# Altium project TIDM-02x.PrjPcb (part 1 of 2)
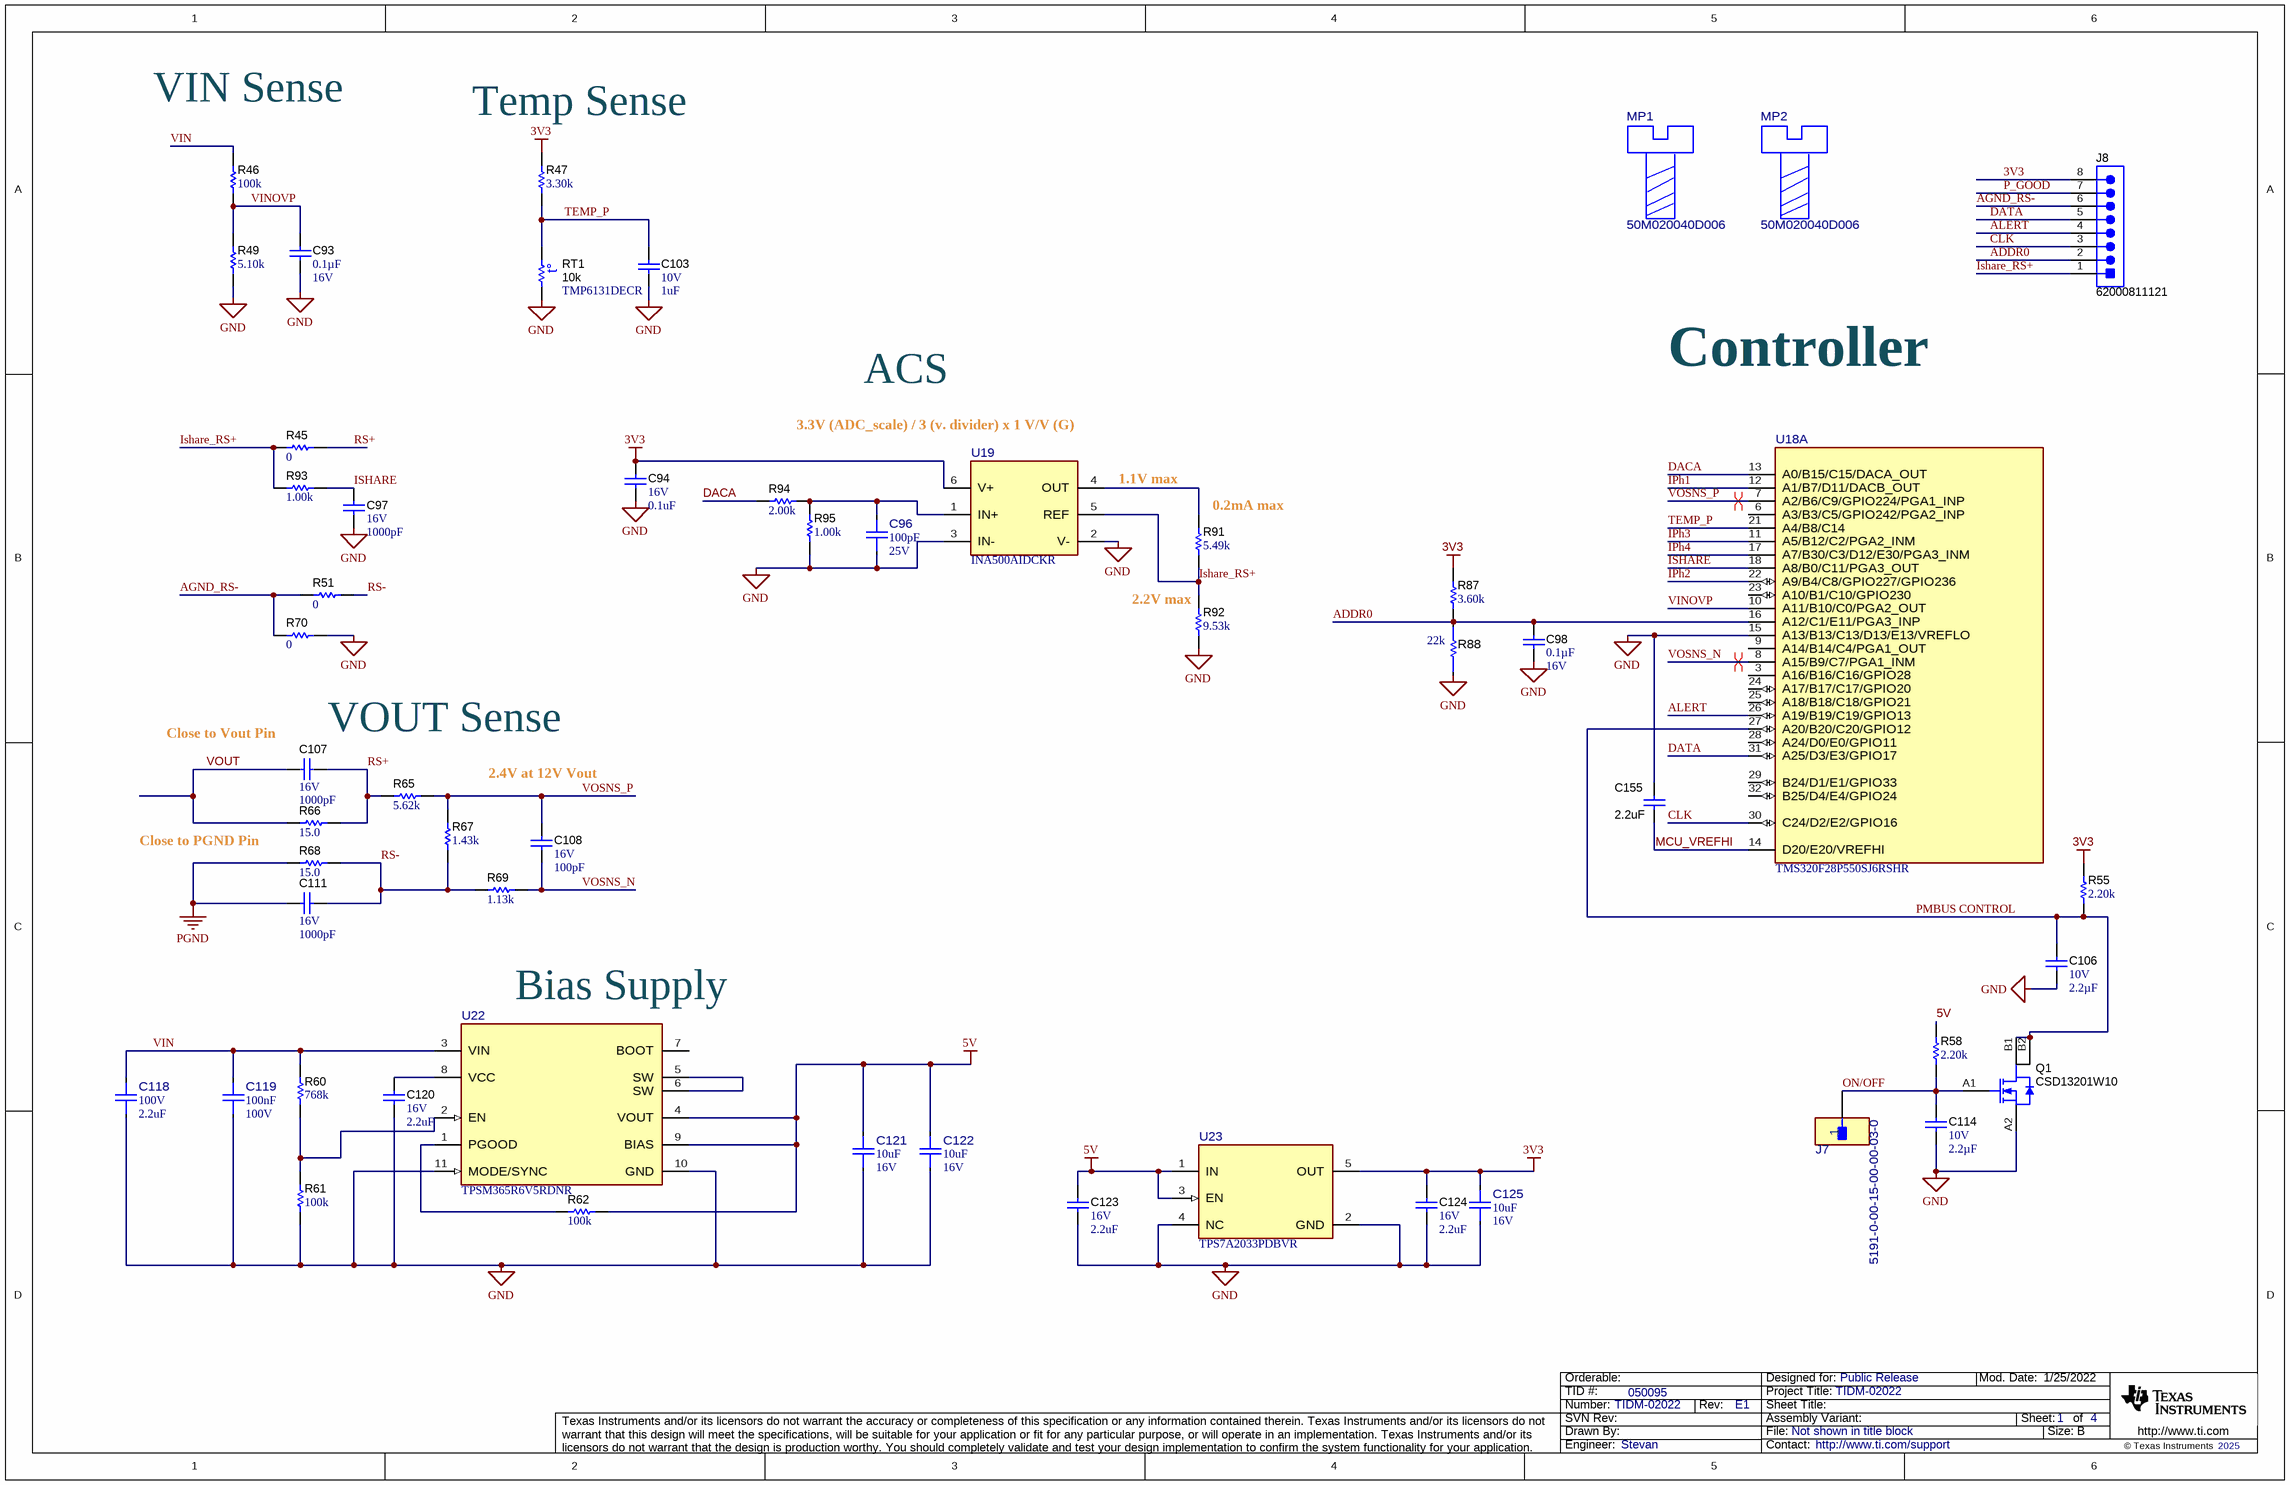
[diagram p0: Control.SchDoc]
CopyrightYear: 2025; PCB_Layout: Stevan; PCB_Rev: E1; PRJ_Customer: Public Release; PRJ_Engineer: Stevan; PRJ_Number: TIDM-02022; PRJ_Title: TIDM-02022; SCH_Rev: E1; TechSupport: http://www.ti.com/support; TID: 050095
4 sheets, 252 parts. Net scope: global (net labels, ports and power ports of the same name join across sheets).
Board file: TIDM-02022.PcbDoc
Sheets:
  Control.SchDoc
  MCU_Support.SchDoc
  PowerStage.SchDoc
  TIDA-05x_Hardware.SchDoc

## Sheet Control.SchDoc
size 431 x 279 mm; Date: Not shown in title block; ApprovedBy: Not shown in title block; CheckedBy: Not shown in title block; Author: Not shown in title block; CompanyName: Not shown in title block; Engineer: Not shown in title block; Organization: Not shown in title block; Address1: Not shown in title block; Address2: Not shown in title block; Address3: Not shown in title block; Address4: Not shown in title block; DocumentNumber: 2; Revision: Use project parameter SCH_Rev; SheetNumber: 1; SheetTotal: 4; PageSetup: Record=PageOptions¦CenterHorizontal=True¦CenterVertical=True¦PrintScale=1.00¦XCorrection=1.00¦YCorrection=1.00¦PrintKind=0¦BorderSize=5000000¦LeftOffset=0¦BottomOffset=0¦Orientation=2¦PaperLength=1000¦PaperWidth=1000¦Scale=100¦PaperSource=15¦PrintQuality=600¦MediaType=1¦DitherType=10¦PaperKind=Letter¦PrintScaleMode=1

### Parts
C93  ValueDisplayed: 0.1µF  VDC_V: 16V  [0201_033]  (hidden comment: 0201BB104KW160)
C94  VDC_V: 16V  ValueDisplayed: 0.1uF  [0201]  (hidden comment: GRM033Z71C104KE14D)
C96  ValueDisplayed: 100pF  VDC_V: 25V  [FP-250R05L101FV4T_0201-MFG]  (hidden comment: 250R05L101FV4T)
C97  VDC_V: 16V  ValueDisplayed: 1000pF  [0201]  (hidden comment: GRM033R71C102KA01D)
C98  ValueDisplayed: 0.1µF  VDC_V: 16V  [0201_033]  (hidden comment: 0201BB104KW160)
C103  VDC_V: 10V  ValueDisplayed: 1uF  [0201]  (hidden comment: CL03A105MP3NSNC)
C106  VDC_V: 10V  ValueDisplayed: 2.2µF  [0201_040]  (hidden comment: GRM033R61A225KE47D)
C107  VDC_V: 16V  ValueDisplayed: 1000pF  [0201_Silk]  (hidden comment: GRM033R71C102KA01D)
C108  VDC_V: 16V  ValueDisplayed: 100pF  [0201]  (hidden comment: GRM033R71C101KA01D)
C111  VDC_V: 16V  ValueDisplayed: 1000pF  [0201_Silk]  (hidden comment: GRM033R71C102KA01D)
C114  VDC_V: 10V  ValueDisplayed: 2.2µF  [0201_040]  (hidden comment: GRM033R61A225KE47D)
C118  VDC_V: 100V  ValueDisplayed: 2.2uF  [FP-12061C225KAT2A_1206-IPC_C]  (hidden comment: 12061C225KAT2A)
C119  Cap_F: 100nF  VDC_V: 100V  [FP-06031C104K4T2A_0603-IPC_C]  (hidden comment: 06031C104K4T2A)
C120  VDC_V: 16V  ValueDisplayed: 2.2uF  [0402S]  (hidden comment: C1005X5R1C225K050BC)
C121  ValueDisplayed: 10uF  VDC_V: 16V  [FP-GRT188R61C106KE13D_0603-MFG]  (hidden comment: GRT188R61C106KE13D)
C122  ValueDisplayed: 10uF  VDC_V: 16V  [FP-GRT188R61C106KE13D_0603-MFG]  (hidden comment: GRT188R61C106KE13D)
C123  VDC_V: 16V  ValueDisplayed: 2.2uF  [0402S]  (hidden comment: C1005X5R1C225K050BC)
C124  VDC_V: 16V  ValueDisplayed: 2.2uF  [0402S]  (hidden comment: C1005X5R1C225K050BC)
C125  ValueDisplayed: 10uF  VDC_V: 16V  [FP-GRT188R61C106KE13D_0603-MFG]  (hidden comment: GRT188R61C106KE13D)
C155  ValueDisplayed: 2.2uF  [0603]  (hidden comment: 885012106018)
J7  5191-0-00-15-00-00-03-0  [FP-5191-0-00-15-00-00-03-0_CONN_PIN-MFG]
J8  62000811121  [Wurth_62000811121]
MP1  50M020040D006  [FP-50M020040D006_M2_NYLON_SCREW-MFG]
MP2  50M020040D006  [FP-50M020040D006_M2_NYLON_SCREW-MFG]
Q1  CSD13201W10  [YZB0004AEAE]
R45  ValueDisplayed: 0  [0201_Silk]  (hidden comment: CRCW02010000Z0ED)
R46  ValueDisplayed: 100k  [0402]  (hidden comment: CRCW0402100KDHEDP)
R47  ValueDisplayed: 3.30k  [0201]  (hidden comment: RC0201FR-073K3L)
R49  ValueDisplayed: 5.10k  [0201]  (hidden comment: RC0201FR-075K1L)
R51  ValueDisplayed: 0  [0201_Silk]  (hidden comment: CRCW02010000Z0ED)
R55  ValueDisplayed: 2.20k  [0201]  (hidden comment: RC0201FR-7D2K2L)
R58  ValueDisplayed: 2.20k  [0201]  (hidden comment: RC0201FR-7D2K2L)
R60  ValueDisplayed: 768k  [0201]  (hidden comment: RC0201FR-07768KL)
R61  ValueDisplayed: 100k  [0201]  (hidden comment: RC0201FR-07100KL)
R62  ValueDisplayed: 100k  [0201]  (hidden comment: RC0201FR-07100KL)
R65  ValueDisplayed: 5.62k  [0201]  (hidden comment: RC0201FR-075K62L)
R66  ValueDisplayed: 15.0  [0201_Silk]  (hidden comment: RC0201FR-0715RL)
R67  ValueDisplayed: 1.43k  [0201]  (hidden comment: RC0201FR-071K43L)
R68  ValueDisplayed: 15.0  [0201_Silk]  (hidden comment: RC0201FR-0715RL)
R69  ValueDisplayed: 1.13k  [0201]  (hidden comment: RC0201FR-071K13L)
R70  ValueDisplayed: 0  [0201_Silk]  (hidden comment: CRCW02010000Z0ED)
R87  ValueDisplayed: 3.60k  [0201]  (hidden comment: RC0201FR-073K6L)
R88  value 22k  [FP-RC0201DR-0722KL_0201-MFG]  (hidden comment: RC0201DR-0722KL)
R91  ValueDisplayed: 5.49k  [0201]  (hidden comment: RC0201FR-075K49L)
R92  ValueDisplayed: 9.53k  [0201]  (hidden comment: RC0201FR-079K53L)
R93  ValueDisplayed: 1.00k  [0201]  (hidden comment: RC0201FR-071KL)
R94  ValueDisplayed: 2.00k  [0201]  (hidden comment: RC0201FR-7D2KL)
R95  ValueDisplayed: 1.00k  [0201]  (hidden comment: RC0201FR-7D1KL)
RT1  value 10k  [DEC0002A-MFG]  (hidden comment: TMP6131DECR)
U18  TMS320F28P550SJ6RSHR  [RSH0056G-MFG]  (part A of 4)
U19  INA500AIDCKR  [DCK0006A-MFG]
U22  TPSM365R6V5RDNR  [RDN0011A-MFG]
U23  TPS7A2033PDBVR  [DBV0005A-MFG]

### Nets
3V3: C94.1 C124.1 C125.2 J8.8 R47.2 R55.2 R87.2 U19.6(V+) U23.5(OUT)
5V: C121.2 C122.2 C123.1 R58.2 R62.1 U22.4(VOUT) U22.9(BIAS) U23.1(IN) U23.3(EN)
GND: C93.2 C94.2 C96.1 C97.2 C98.2 C103.2 C106.2 C114.2 C118.1 C119.1 C120.2 C121.1 C122.1 C123.2 C124.2 C125.1 C155.1 Q1.A2(S) R49.1 R61.1 R70.2 R88.1 R92.1 R95.1 RT1.1 U18.15(A13/B13/C13/D13/E13/VREFLO) U19.2(V-) U19.3(IN-) U22.10(GND) U22.11(MODE/SYNC) U23.2(GND) U23.4(NC)
PGND: C111.2 R68.1
VIN: C118.2 C119.2 R46.2 R60.2 U22.3(VIN)
ADDR0: C98.1 J8.2 R87.1 R88.2 U18.16(A12/C1/E11/PGA3_INP)
AGND_RS-: J8.6 R51.1 R70.1
ALERT: J8.4 U18.26(A19/B19/C19/GPIO13)
CLK: J8.3 U18.30(C24/D2/E2/GPIO16)
DACA: R94.1 U18.13(A0/B15/C15/DACA_OUT)
DATA: J8.5 U18.31(A25/D3/E3/GPIO17)
IPh1: U18.12(A1/B7/D11/DACB_OUT)
IPh2: U18.22(A9/B4/C8/GPIO227/GPIO236)
IPh3: U18.11(A5/B12/C2/PGA2_INM)
IPh4: U18.17(A7/B30/C3/D12/E30/PGA3_INM)
ISHARE: C97.1 R93.1 U18.18(A8/B0/C11/PGA3_OUT)
Ishare_RS+: J8.1 R45.1 R91.1 R92.2 R93.2 U19.5(REF)
MCU_VREFHI: C155.2 U18.14(D20/E20/VREFHI)
ON/OFF: C114.1 J7.1 Q1.A1(G) R58.1
P_GOOD: J8.7
PMBUS CONTROL: C106.1 Q1.B1(D) Q1.B2(D) R55.1 U18.27(A20/B20/C20/GPIO12)
RS+: C107.1 R45.2 R65.1 R66.2
RS-: C111.1 R51.2 R67.1 R68.2 R69.1
TEMP_P: C103.1 R47.1 RT1.2 U18.21(A4/B8/C14)
VINOVP: C93.1 R46.1 R49.2 U18.10(A11/B10/C0/PGA2_OUT)
VOSNS_N: C108.2 R69.2 U18.8(A15/B9/C7/PGA1_INM)
VOSNS_P: C108.1 R65.2 R67.2 U18.7(A2/B6/C9/GPIO224/PGA1_INP)
VOUT: C107.2 R66.1
NetC96_2: C96.2 R94.2 R95.2 U19.1(IN+)
NetC120_1: C120.1 U22.8(VCC)
NetR60_1: R60.1 R61.2 U22.2(EN)
NetR62_2: R62.2 U22.1(PGOOD)
NetR91_2: R91.2 U19.4(OUT)
NetU22_5: U22.5(SW) U22.6(SW)

Not connected (* = marked no-connect by the designer): U18 3(A16/B16/C16/GPIO28) 6(A3/B3/C5/GPIO242/PGA2_INP) 9(A14/B14/C4/PGA1_OUT) 23(A10/B1/C10/GPIO230) 24(A17/B17/C17/GPIO20) 25(A18/B18/C18/GPIO21) 28(A24/D0/E0/GPIO11) 29(B24/D1/E1/GPIO33) 32(B25/D4/E4/GPIO24); U22 7(BOOT)

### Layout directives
differential pair: VOSNS_N, VOSNS_P

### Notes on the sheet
- VIN Sense
- (near R47) Temp Sense
- 3.3V (ADC_scale) / 3 (v. divider) x 1 V/V (G)
- ACS
- Controller
- 1.1V max
- (near R91) 0.2mA max
- (near R92) 2.2V max
- (near C107) Close to Vout Pin
- (near C107) VOUT Sense
- 2.4V at 12V Vout
- Close to PGND Pin
- (near U22) Bias Supply

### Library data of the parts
C93 C98 = CMP-0860981-1: CAP, CERM, 0.1 µF, 16 V,+/- 10%, X7R, 0201; Manufacturer: Passive Plus; Value: 0.1uF; Polarized: N; SizeY_mm: 0.3; TaMin_C: -55°C; U/M: EA; Cap_Case: 0201; AEC Category: Q200; SizeZ_mm: 0.33; SizeArea_mm2: 0.18; SizeX_mm: 0.6; Cap_F: 100nF; SizeAreaWB_mm2: 2.08; TaMax_C: 125°C
C94 = CMP-0064970-1: CAP, CERM, 0.1 uF, 16 V,+/- 10%, X7R, 0201; Manufacturer: MuRata; TaMin_C: -55°C; Polarized: N; SizeAreaWB_mm2: 2.08; Value1: Unknown; U/M: EA; Value: 0.1uF; TaMax_C: 125°C; SizeZ_mm: 0.26; SizeX_mm: 0.6; SizeY_mm: 0.3; SizeArea_mm2: 0.18; Cap_F: 100nF; AEC Category: Q200
C96 = CMP-0092339-1: 100pF ±1% 25V Ceramic Capacitor C0G, NP0 0201 (0603 Metric); Manufacturer: Johanson; AEC Qualified: No; SizeZ_mm: 0.33mm; TempCo: 30ppm/°C
C97 = CMP-0009745-1: CAP, CERM, 1000 pF, 16 V, +/- 10%, X7R, 0201; Manufacturer: MuRata; TaMin_C: -55°C; Polarized: N; SizeAreaWB_mm2: 2.08; Value1: Unknown; U/M: EA; Value: 1000pF; TaMax_C: 125°C; SizeZ_mm: 0.26; SizeX_mm: 0.6; SizeY_mm: 0.3; SizeArea_mm2: 0.18; Cap_F: 1nF; AEC Category: Q200
C103 = CMP-0009656-3: CAP, CERM, 1 uF, 10 V, +/- 20%, X5R, 0201; Manufacturer: Samsung Electro-Mechanics; TaMin_C: -55°C; Polarized: N; SizeAreaWB_mm2: 2.08; Value1: Unknown; U/M: EA; Value: 1uF; TaMax_C: 85°C; SizeZ_mm: 0.26; SizeX_mm: 0.6; SizeY_mm: 0.3; SizeArea_mm2: 0.18; Cap_F: 1µF; AEC Category: Q200
C106 C114 = CMP-0081160-1: CAP, CERM, 2.2 µF, 10 V,+/- 10%, X5R, 0201; Manufacturer: MuRata; SizeAreaWB_mm2: 2.08; SizeArea_mm2: 0.18; AEC Qualified: N; AEC Category: Q200; Value: 2.2uF; TaMax_C: 85°C; SizeZ_mm: 0.4; TaMin_C: -55°C; SizeY_mm: 0.3; U/M: EA; SizeX_mm: 0.6; Cap_Case: 0201
C107 C111 = CMP-0009745-1: CAP, CERM, 1000 pF, 16 V, +/- 10%, X7R, 0201; Manufacturer: MuRata; TaMin_C: -55°C; Polarized: N; SizeAreaWB_mm2: 2.08; Value1: Unknown; U/M: EA; Value: 1000pF; TaMax_C: 125°C; SizeZ_mm: 0.26; SizeX_mm: 0.6; SizeY_mm: 0.3; Cap_Case: 0201; SizeArea_mm2: 0.18; Cap_F: 1nF; AEC Category: Q200
C108 = CMP-0009744-1: CAP, CERM, 100 pF, 16 V, +/- 10%, X7R, 0201; Manufacturer: MuRata; TaMin_C: -55°C; Polarized: N; SizeAreaWB_mm2: 2.08; Value1: Unknown; U/M: EA; Value: 100pF; TaMax_C: 125°C; SizeZ_mm: 0.26; SizeX_mm: 0.6; SizeY_mm: 0.3; SizeArea_mm2: 0.18; AEC Category: Q200
C118 = CMP-0092494-1: 2.2uF @ ±10% 100V Ceramic Capacitor X7R 15% 1206 (3216 Metric); Manufacturer: AVX; SizeZ_mm: 1.78mm; AEC Qualified: No; Value: 2.2µF
C119 = CMP-0094779-1: Cap Ceramic 100nF 100V X7R 10% SMD 0603 125°C Paper T/R; Manufacturer: KYOCERA AVX; AEC Grade: Grade 1; SizeZ_mm: 0.94mm; AEC Qualified: Yes; TempCo: 15%
C120 C123 C124 = CMP-0006275-2: CAP, CERM, 2.2 uF, 16 V, +/- 10%, X5R, 0402; Manufacturer: TDK; TaMin_C: -55°C; Polarized: N; SizeAreaWB_mm2: 3; Value1: Unknown; U/M: EA; Value: 2.2uF; TaMax_C: 85°C; SizeZ_mm: 0.6; SizeX_mm: 1; SizeY_mm: 0.5; Cap_Case: 0402; Cap_F: 2.2µF; AEC Category: Q200
C121 C122 C125 = CMP-0126314-1: Multi-Layer Ceramic Capacitor 10uF 16V X5R ±10% 0603 Paper T/R; Manufacturer: Murata; AEC Grade: Grade 3; AEC Qualified: Yes; Cap_F: 10µF; SizeZ_mm: 0.95mm; TempCo: 15%; Value: 10µF
C155 = CMP-0006825-5: CAP, CERM, 2.2 uF, 16 V, +/- 20%, X5R, 0603; Manufacturer: Wurth Elektronik; TaMin_C: -55°C; Polarized: N; SizeAreaWB_mm2: 4.68; Value1: Unknown; U/M: EA; Value: 2.2uF; TaMax_C: 85°C; SizeZ_mm: 1; SizeX_mm: 1.6; SizeY_mm: 0.8; Value2: 16V; SizeArea_mm2: 1.28; Cap_F: 2.2µF; AEC Category: Q200
J7 = CMP-0125276-1: PC Pin Terminal Connector Through Hole Gold 0.060" (1.52mm) Dia; Manufacturer: Mill-Max; ContactFinish: Gold,Nickel; Conn Gender: Male; Conn Orientation: Straight
J8 = CMP-0054807-1: Header, 2 mm, 8x1, Gold,TH; Manufacturer: Wurth Elektronik; CNHeader: TRUE; Shrouded: N; Gender: Male; Row_Count: 1; Pitch_mm: 2; CT: FALSE
MP1 MP2 = CMP-0086543-1: Nylon M2 X .4 Cheese Head Slotted Machine Screw; Manufacturer: Essentra Components
Q1 = CMP-0000192-1: MOSFET, N-CH, 12 V, 1.6 A, YZB0004AEAE (DSBGA-4); Alternate Manufacturer: None; Manufacturer: Texas Instruments; SizeZ_mm: 1; ChType: N; Value2: 2.3 nC; Value1: 0.02; VdsMax_V: 12V; SizeX_mm: 1.25; SizeAreaWB_mm2: 5.0625; Vgs_V: 8V; QgTyp_nC: 2.3; Value: 12V; Rdson45_ohm: 26m; SizeArea_mm2: 1.5625; AEC Category: Q101; IdsMax_A: 1.6A; U/M: EA
R45 R51 R70 = CMP-0027008-4: RES, 0, 5%, 0.05 W, 0201; Manufacturer: Vishay-Dale; Power_W: 50mW; TempCo: ppm/C; Value_Code: 0000; Value: 0; EIA_Code: E24; SizeX_mm: 0.6; SizeY_mm: 0.3; SizeZ_mm: 0.26; Value2: 0.05W; SizeArea_mm2: 0.18; AEC Qualified: N; AEC Category: Q200
R46 = CMP-0026768-2: RES, 100 k, 0.5%, 0.063 W, AEC-Q200 Grade 0, 0402; Manufacturer: Vishay-Dale; Power_W: 63mW; TempCo: 50 ppm/C; Value: 100k; EIA_Code: E192; SizeX_mm: 1; SizeY_mm: 0.5; SizeZ_mm: 0.6; Value2: 0.063W; AEC Qualified: Y; VDC_V: 50V; AEC Category: Q200; AEC Grade: 0
R47 = CMP-0027657-1: RES, 3.30 k, 1%, 0.05 W, 0201; Manufacturer: Yageo America; Power_W: 50mW; TempCo: 200 ppm/C; Value_Code: 3k30; U/M: EA; Value: 3.30k; Res_ohm: 3.3k; SizeX_mm: 0.6; SizeY_mm: 0.3; SizeZ_mm: 0.26; Value2: 0.05W; SizeArea_mm2: 0.18; AEC Qualified: N; VDC_V: 25V; AEC Category: Q200
R49 = CMP-0027789-1: RES, 5.10 k, 1%, 0.05 W, 0201; Manufacturer: Yageo America; Power_W: 50mW; TempCo: 200 ppm/C; Value_Code: 5k10; U/M: EA; Value: 5.10k; Res_ohm: 5.1k; SizeX_mm: 0.6; SizeY_mm: 0.3; SizeZ_mm: 0.26; Value2: 0.05W; SizeArea_mm2: 0.18; AEC Qualified: N; VDC_V: 25V; AEC Category: Q200
R55 R58 = CMP-0027995-1: RES, 2.20 k, 1%, 0.05 W, 0201; Manufacturer: Yageo America; Power_W: 50mW; TempCo: 200 ppm/C; Value_Code: 2k20; U/M: EA; Value: 2.20k; Res_ohm: 2.2k; SizeX_mm: 0.6; SizeY_mm: 0.3; SizeZ_mm: 0.26; Value2: 0.05W; SizeArea_mm2: 0.18; AEC Qualified: N; VDC_V: 25V; AEC Category: Q200
R60 = CMP-0027868-1: RES, 768 k, 1%, 0.05 W, 0201; Manufacturer: Yageo America; Power_W: 50mW; TempCo: 200 ppm/C; U/M: EA; Value: 768k; EIA_Code: E96; SizeX_mm: 0.6; SizeY_mm: 0.3; SizeZ_mm: 0.26; Value2: 0.05W; SizeArea_mm2: 0.18; AEC Qualified: N; VDC_V: 25V; AEC Category: Q200
R61 R62 = CMP-0027293-2: RES, 100 k, 1%, 0.05 W, 0201; Manufacturer: Yageo America; Power_W: 50mW; TempCo: 200 ppm/C; U/M: EA; Value: 100k; EIA_Code: E96; SizeX_mm: 0.6; SizeY_mm: 0.3; SizeZ_mm: 0.26; Value2: 0.05W; SizeArea_mm2: 0.18; AEC Qualified: N; VDC_V: 25V; AEC Category: Q200
R65 = CMP-0027793-1: RES, 5.62 k, 1%, 0.05 W, 0201; Manufacturer: Yageo America; Power_W: 50mW; TempCo: 200 ppm/C; Value_Code: 5k62; U/M: EA; Value: 5.62k; EIA_Code: E96; SizeX_mm: 0.6; SizeY_mm: 0.3; SizeZ_mm: 0.26; Value2: 0.05W; SizeArea_mm2: 0.18; AEC Qualified: N; VDC_V: 25V; AEC Category: Q200
R66 R68 = CMP-0027377-2: RES, 15.0, 1%, 0.05 W, 0201; Manufacturer: Yageo America; Power_W: 50mW; TempCo: 200 ppm/C; Value_Code: 15R0; U/M: EA; Value: 15.0; EIA_Code: E96; Res_ohm: 15; SizeX_mm: 0.6; SizeY_mm: 0.3; SizeZ_mm: 0.26; Value2: 0.05W; SizeArea_mm2: 0.18; AEC Qualified: N; VDC_V: 25V; AEC Category: Q200
R67 = CMP-0027436-1: RES, 1.43 k, 1%, 0.05 W, 0201; Manufacturer: Yageo America; Power_W: 50mW; TempCo: 200 ppm/C; Value_Code: 1k43; U/M: EA; Value: 1.43k; EIA_Code: E96; SizeX_mm: 0.6; SizeY_mm: 0.3; SizeZ_mm: 0.26; Value2: 0.05W; SizeArea_mm2: 0.18; AEC Qualified: N; VDC_V: 25V; AEC Category: Q200
R69 = CMP-0027425-1: RES, 1.13 k, 1%, 0.05 W, 0201; Manufacturer: Yageo America; Power_W: 50mW; TempCo: 200 ppm/C; Value_Code: 1k13; U/M: EA; Value: 1.13k; EIA_Code: E96; SizeX_mm: 0.6; SizeY_mm: 0.3; SizeZ_mm: 0.26; Value2: 0.05W; SizeArea_mm2: 0.18; AEC Qualified: N; VDC_V: 25V; AEC Category: Q200
R87 = CMP-0027662-1: RES, 3.60 k, 1%, 0.05 W, 0201; Manufacturer: Yageo America; Power_W: 50mW; TempCo: 200 ppm/C; Value_Code: 3k60; U/M: EA; Value: 3.60k; Res_ohm: 3.6k; SizeX_mm: 0.6; SizeY_mm: 0.3; SizeZ_mm: 0.26; Value2: 0.05W; SizeArea_mm2: 0.18; AEC Qualified: N; VDC_V: 25V; AEC Category: Q200
R88 = CMP-0126318-1: 22 kOhms ±0.5% 0.05W, 1/20W Chip Resistor 0201 (0603 Metric) Moisture Resistant Thick Film; Manufacturer: YAGEO; AEC Qualified: No; Power_W: 50mW; SizeZ_mm: 0.26mm; TempCo: 200ppm/°C; VDC_V: 25V; Standoff Height: 0mm
R91 = CMP-0027792-1: RES, 5.49 k, 1%, 0.05 W, 0201; Manufacturer: Yageo America; Power_W: 50mW; TempCo: 200 ppm/C; Value_Code: 5k49; U/M: EA; Value: 5.49k; EIA_Code: E96; SizeX_mm: 0.6; SizeY_mm: 0.3; SizeZ_mm: 0.26; Value2: 0.05W; SizeArea_mm2: 0.18; AEC Qualified: N; VDC_V: 25V; AEC Category: Q200
R92 = CMP-0027939-1: RES, 9.53 k, 1%, 0.05 W, 0201; Manufacturer: Yageo America; Power_W: 50mW; TempCo: 200 ppm/C; Value_Code: 9k53; U/M: EA; Value: 9.53k; EIA_Code: E96; SizeX_mm: 0.6; SizeY_mm: 0.3; SizeZ_mm: 0.26; Value2: 0.05W; SizeArea_mm2: 0.18; AEC Qualified: N; VDC_V: 25V; AEC Category: Q200
R93 = CMP-0027453-1: RES, 1.00 k, 1%, 0.05 W, 0201; Manufacturer: Yageo America; Power_W: 50mW; TempCo: 200 ppm/C; Value_Code: 1k00; U/M: EA; Value: 1.00k; EIA_Code: E96; Res_ohm: 1k; SizeX_mm: 0.6; SizeY_mm: 0.3; SizeZ_mm: 0.26; Value2: 0.05W; SizeArea_mm2: 0.18; AEC Qualified: N; VDC_V: 25V; AEC Category: Q200
R94 = CMP-0028000-1: RES, 2.00 k, 1%, 0.05 W, 0201; Manufacturer: Yageo America; Power_W: 50mW; TempCo: 200 ppm/C; Value_Code: 2k00; U/M: EA; Value: 2.00k; EIA_Code: E96; Res_ohm: 2k; SizeX_mm: 0.6; SizeY_mm: 0.3; SizeZ_mm: 0.26; Value2: 0.05W; SizeArea_mm2: 0.18; AEC Qualified: N; VDC_V: 25V; AEC Category: Q200
R95 = CMP-0027973-1: RES, 1.00 k, 1%, 0.05 W, 0201; Manufacturer: Yageo America; Power_W: 50mW; TempCo: 200 ppm/C; Value_Code: 1k00; U/M: EA; Value: 1.00k; EIA_Code: E96; Res_ohm: 1k; SizeX_mm: 0.6; SizeY_mm: 0.3; SizeZ_mm: 0.26; Value2: 0.05W; SizeArea_mm2: 0.18; AEC Qualified: N; VDC_V: 25V; AEC Category: Q200
RT1 = CMP-0123214-2: ±1% tolerance 10kΩ linear thermistor available in 0402 and 0603 package options 2-X1SON -40 to 125; Manufacturer: Texas Instruments; SizeZ_mm: 0.5mm; AEC Qualified: No; Standoff Height: 0mm; TaMax_C: +125°C; TaMin_C: -40°C; TJmax_C: +155°C; VDC_V: 5.5V; AEC Category: Q200; CompType: IC
U18 = CMP-0122591-1: Real-Time Microcontrollers; Manufacturer: Texas Instruments; SizeZ_mm: 1mm; AEC Qualified: No; Core Architecture: C28x; Data Bus Width: 32bits; Frequency_Fixed: 150MHz; Interface: I2C,SPI,UART,CAN,USB,LIN,SCI,SMBus; Max Supply Voltage: 3.63V; Memory Size: 1MBytes; Memory Type: FLASH; Min Supply Voltage: 1.14V; Number Of A/D Converters: 5; Number Of Adc Channels: 26; Number Of Cores: 1; Number Of I/Os: 15; Number Of I2C Channels: 2; Number Of Pwm Channels: 24; Number Of Timers/Counters: 3; Ram Size: 133KBytes; Standoff Height: 0mm; TaMax_C: +125°C; TaMin_C: -40°C; TJmax_C: +150°C
U19 = CMP-0126255-1: Low-power, 1-MΩ RIN, 20-µA IQ, small-size attenuating difference amplifier 6-SC70 -40 to 125; Manufacturer: Texas Instruments; SizeZ_mm: 1.1mm; AEC Qualified: No; Bandwidth: 125kHz; Max Dual Supply Voltage: 2.75V; Max Supply Voltage: 5.5V; Min Dual Supply Voltage: 850mV; Min Supply Voltage: 1.7V; Nominal Supply Current: 13.5-14.5uA; Number Of Channels: 1; Output Current Per Channel: 33mA; Response Time: 43us; Standoff Height: 0mm; TaMax_C: +150°C; TaMin_C: -55°C
U22 = CMP-0098344-1: 3-V to 65-V Input, 1-V to 13-V Output, 600-mA Synchronous Buck Converter Power Module in a HotRod QFN Package; Manufacturer: Texas Instruments; SizeZ_mm: 2.1mm; AEC Qualified: No; Max Duty Cycle: 98%; Max Supply Voltage: 65V; Min Supply Voltage: 3.6V; Number Of Outputs: 1; Output Type: Fixed; Output Voltage: 5V; Standoff Height: 0mm; Switching Frequency: 1MHz; TJmax_C: +125°C
U23 = CMP-0092532-1: 300-mA, Ultra-Low-Noise, Low-IQ, High PSRR LDO; Manufacturer: Texas Instruments; TJmax_C: +125°C; Min Supply Voltage: 1.6V; SizeZ_mm: 1.45mm; Output Voltage: 3.3V; Number Of Outputs: 1; Nominal Supply Current: 6.5uA; AEC Qualified: No; Accuracy Percentage: 1.5%; Max Supply Voltage: 6V; Dropout Voltage: 145mV; Standoff Height: 0mm; Output Type: Fixed

## Sheet MCU_Support.SchDoc
size 431 x 279 mm; Date: Not shown in title block; ApprovedBy: Not shown in title block; CheckedBy: Not shown in title block; Author: Not shown in title block; CompanyName: Not shown in title block; Engineer: Not shown in title block; Organization: Not shown in title block; Address1: Not shown in title block; Address2: Not shown in title block; Address3: Not shown in title block; Address4: Not shown in title block; DocumentNumber: 4; Revision: Use project parameter SCH_Rev; SheetNumber: 2; SheetTotal: 4; PageSetup: Record=PageOptions¦CenterHorizontal=True¦CenterVertical=True¦PrintScale=1.00¦XCorrection=1.00¦YCorrection=1.00¦PrintKind=0¦BorderSize=5000000¦LeftOffset=0¦BottomOffset=0¦Orientation=2¦PaperLength=1000¦PaperWidth=1000¦Scale=100¦PaperSource=15¦PrintQuality=600¦MediaType=1¦DitherType=10¦PaperKind=Letter¦PrintScaleMode=1
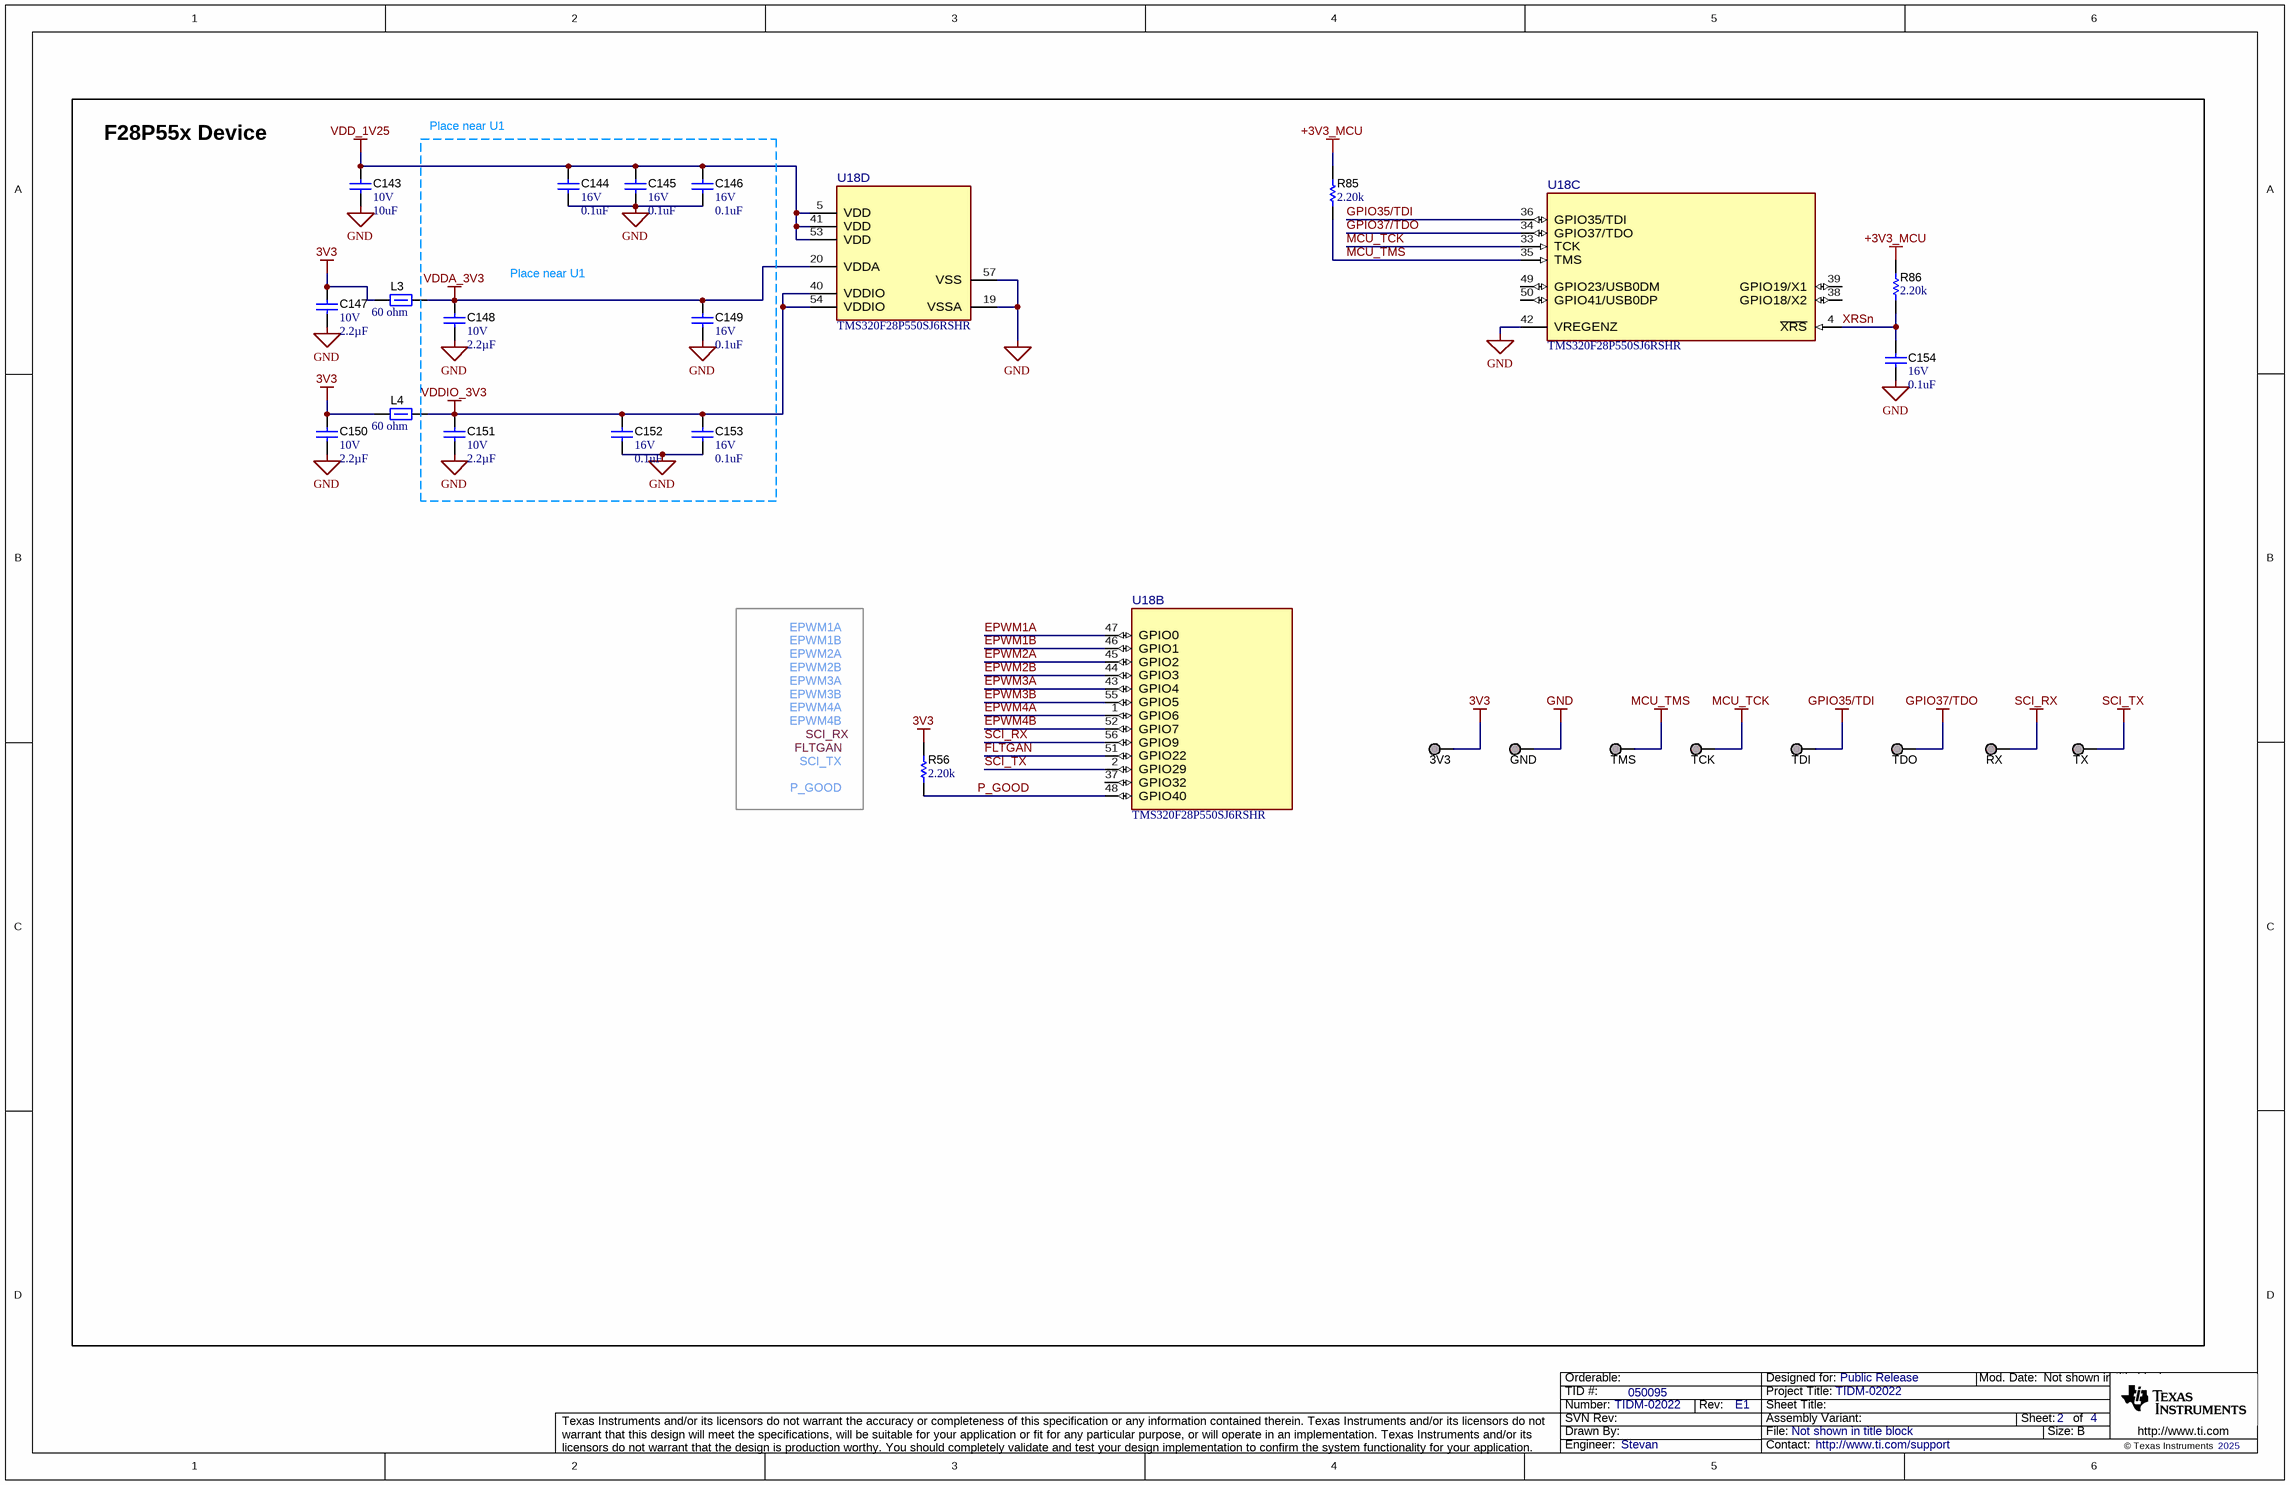
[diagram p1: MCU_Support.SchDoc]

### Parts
3V3  TP_SM_1MM  [TP_SM_1MM]  (value not drawn)  (no BOM)
C143  VDC_V: 10V  ValueDisplayed: 10uF  [0402_070]  (hidden comment: GRM155R61A106ME21D)
C144  VDC_V: 16V  ValueDisplayed: 0.1uF  [0201]  (hidden comment: GRM033Z71C104KE14D)
C145  VDC_V: 16V  ValueDisplayed: 0.1uF  [0201]  (hidden comment: GRM033Z71C104KE14D)
C146  VDC_V: 16V  ValueDisplayed: 0.1uF  [0201]  (hidden comment: GRM033Z71C104KE14D)
C147  VDC_V: 10V  ValueDisplayed: 2.2µF  [0201_040]  (hidden comment: GRM033R61A225KE47D)
C148  VDC_V: 10V  ValueDisplayed: 2.2µF  [0201_040]  (hidden comment: GRM033R61A225KE47D)
C149  VDC_V: 16V  ValueDisplayed: 0.1uF  [0201]  (hidden comment: GRM033Z71C104KE14D)
C150  VDC_V: 10V  ValueDisplayed: 2.2µF  [0201_040]  (hidden comment: GRM033R61A225KE47D)
C151  VDC_V: 10V  ValueDisplayed: 2.2µF  [0201_040]  (hidden comment: GRM033R61A225KE47D)
C152  VDC_V: 16V  ValueDisplayed: 0.1uF  [0201]  (hidden comment: GRM033Z71C104KE14D)
C153  VDC_V: 16V  ValueDisplayed: 0.1uF  [0201]  (hidden comment: GRM033Z71C104KE14D)
C154  VDC_V: 16V  ValueDisplayed: 0.1uF  [0201]  (hidden comment: GRM033Z71C104KE14D)
GND  TP_SM_1MM  [TP_SM_1MM]  (value not drawn)  (no BOM)
L3  value 60 ohm  [0603]  (hidden comment: 742792602)
L4  value 60 ohm  [0603]  (hidden comment: 742792602)
R56  ValueDisplayed: 2.20k  [0201]  (hidden comment: RC0201FR-7D2K2L)
R85  ValueDisplayed: 2.20k  [0201]  (hidden comment: RC0201FR-7D2K2L)
R86  ValueDisplayed: 2.20k  [0201]  (hidden comment: RC0201FR-7D2K2L)
RX  TP_SM_1MM  [TP_SM_1MM]  (value not drawn)  (no BOM)
TCK  TP_SM_1MM  [TP_SM_1MM]  (value not drawn)  (no BOM)
TDI  TP_SM_1MM  [TP_SM_1MM]  (value not drawn)  (no BOM)
TDO  TP_SM_1MM  [TP_SM_1MM]  (value not drawn)  (no BOM)
TMS  TP_SM_1MM  [TP_SM_1MM]  (value not drawn)  (no BOM)
TX  TP_SM_1MM  [TP_SM_1MM]  (value not drawn)  (no BOM)
U18  TMS320F28P550SJ6RSHR  [RSH0056G-MFG]  (parts B,C,D of 4)

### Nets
3V3: 3V3.1 C147.1 C150.1 L3.1 L4.1 R56.2
+3V3_MCU: R85.2 R86.2
GND: C143.2 C144.2 C145.2 C146.2 C147.2 C148.2 C149.2 C150.2 C151.2 C152.2 C153.2 C154.2 GND.1 U18.19(VSSA) U18.42(VREGENZ) U18.57(VSS)
GPIO35/TDI: TDI.1 U18.36(GPIO35/TDI)
GPIO37/TDO: TDO.1 U18.34(GPIO37/TDO)
MCU_TCK: TCK.1 U18.33(TCK)
MCU_TMS: R85.1 TMS.1 U18.35(TMS)
SCI_RX: RX.1 U18.56(GPIO9)
SCI_TX: TX.1 U18.2(GPIO29)
VDD_1V25: C143.1 C144.1 C145.1 C146.1 U18.5(VDD) U18.41(VDD) U18.53(VDD)
VDDA_3V3: C148.1 C149.1 L3.2 U18.20(VDDA)
VDDIO_3V3: C151.1 C152.1 C153.1 L4.2 U18.40(VDDIO) U18.54(VDDIO)
EPWM1A: U18.47(GPIO0)
EPWM1B: U18.46(GPIO1)
EPWM2A: U18.45(GPIO2)
EPWM2B: U18.44(GPIO3)
EPWM3A: U18.43(GPIO4)
EPWM3B: U18.55(GPIO5)
EPWM4A: U18.1(GPIO6)
EPWM4B: U18.52(GPIO7)
FLTGAN: U18.51(GPIO22)
P_GOOD: R56.1 U18.48(GPIO40)
XRSn: C154.1 R86.1 U18.4(~{XRS})

Not connected (* = marked no-connect by the designer): U18 37(GPIO32) 38(GPIO18/X2) 39(GPIO19/X1) 49(GPIO23/USB0DM) 50(GPIO41/USB0DP)

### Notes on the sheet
- F28P55x Device
- Place near U1
- EPWM1A
- EPWM3A
- EPWM3B
- EPWM1B
- EPWM2A
- EPWM2B
- FLTGAN
- SCI_TX
- EPWM4A
- EPWM4B
- SCI_RX
- P_GOOD

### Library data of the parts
3V3 GND RX TCK TDI TDO TMS TX = CMP-0003825-1: 1mm Test Point, SMT; Manufacturer: Any
C143 = CMP-0006565-2: CAP, CERM, 10 uF, 10 V, +/- 20%, X5R, 0402; Manufacturer: MuRata; TaMin_C: -55°C; Polarized: N; SizeAreaWB_mm2: 3; Value1: Unknown; U/M: EA; Value: 10uF; TaMax_C: 85°C; SizeZ_mm: 0.7; SizeX_mm: 1; SizeY_mm: 0.5; Cap_Case: 0402; Cap_F: 10µF; AEC Category: Q200
C144-C146 C149 C152-C154 = CMP-0064970-1: as C94 on sheet Control
C147 C148 C150 C151 = CMP-0081160-1: as C106 on sheet Control
L3 L4 = CMP-0003173-2: Ferrite Bead, 60 ohm @ 100 MHz, 3 A, 0603; Manufacturer: Wurth Elektronik; Ztyp@1GHz_Ohm: 110.436; ZTyp@100MHz_Ohm: 60; SizeAreaWB_mm2: 4.68; DCR_ohm: 0.04; Value1: 0.04 ohm; Imax_A: 3A; SizeZ_mm: 1; SizeX_mm: 1.6; SizeY_mm: 0.8; SizeArea_mm2: 1.28
R56 R85 R86 = CMP-0027995-1: as R55 on sheet Control
U18 = CMP-0122591-1: as U18 on sheet Control

## Sheet PowerStage.SchDoc
size 660 x 279 mm; Date: Not shown in title block; ApprovedBy: Not shown in title block; CheckedBy: Not shown in title block; Author: Not shown in title block; CompanyName: Not shown in title block; Engineer: Not shown in title block; Organization: Not shown in title block; Address1: Not shown in title block; Address2: Not shown in title block; Address3: Not shown in title block; Address4: Not shown in title block; DocumentNumber: 1; Revision: Use project parameter SCH_Rev; SheetNumber: 3; SheetTotal: 4; PageSetup: Record=PageOptions¦CenterHorizontal=True¦CenterVertical=True¦PrintScale=1.00¦XCorrection=1.00¦YCorrection=1.00¦PrintKind=0¦BorderSize=5000000¦LeftOffset=0¦BottomOffset=0¦Orientation=2¦PaperLength=1000¦PaperWidth=1000¦Scale=100¦PaperSource=15¦PrintQuality=600¦MediaType=1¦DitherType=10¦PaperKind=Letter¦PrintScaleMode=1
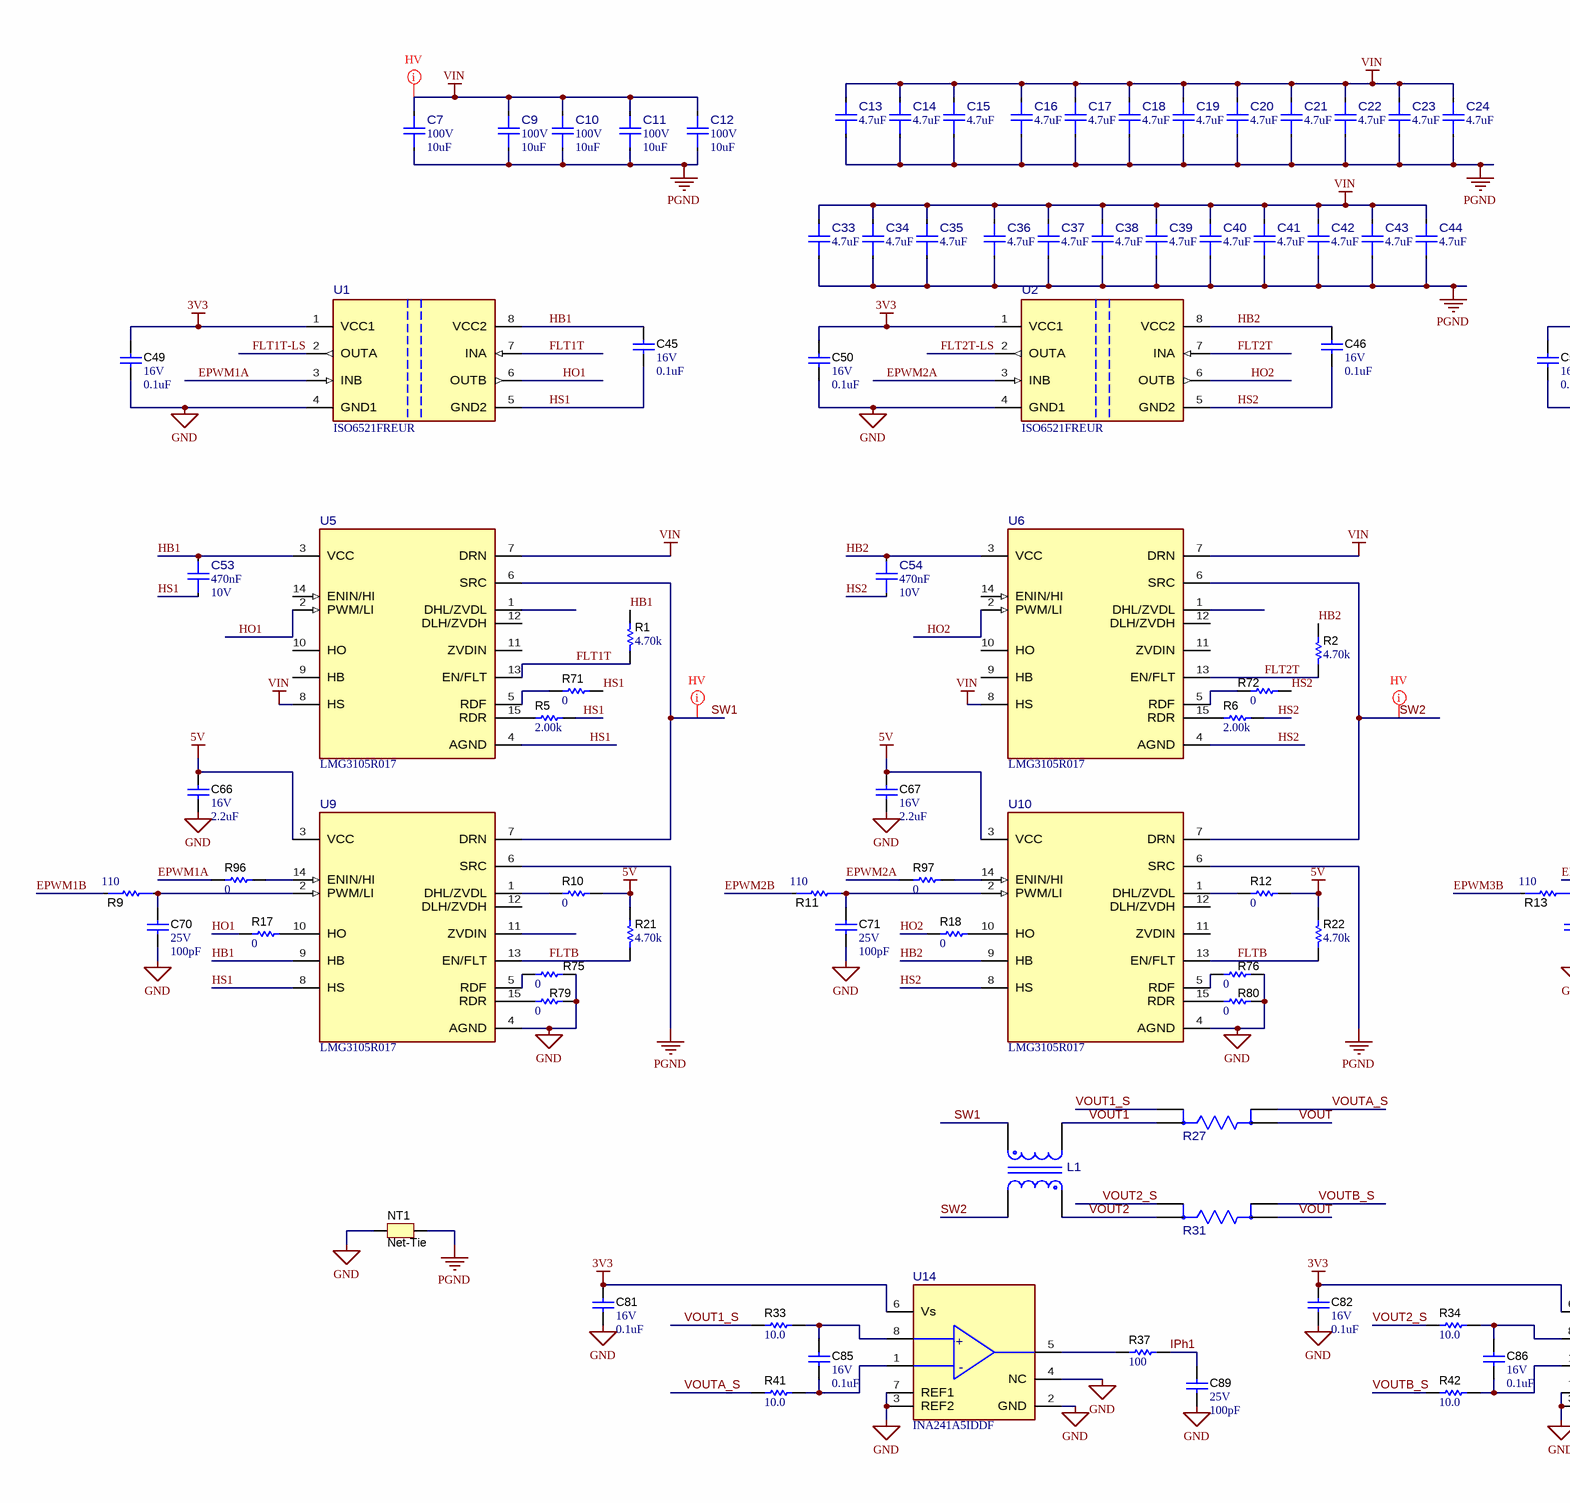
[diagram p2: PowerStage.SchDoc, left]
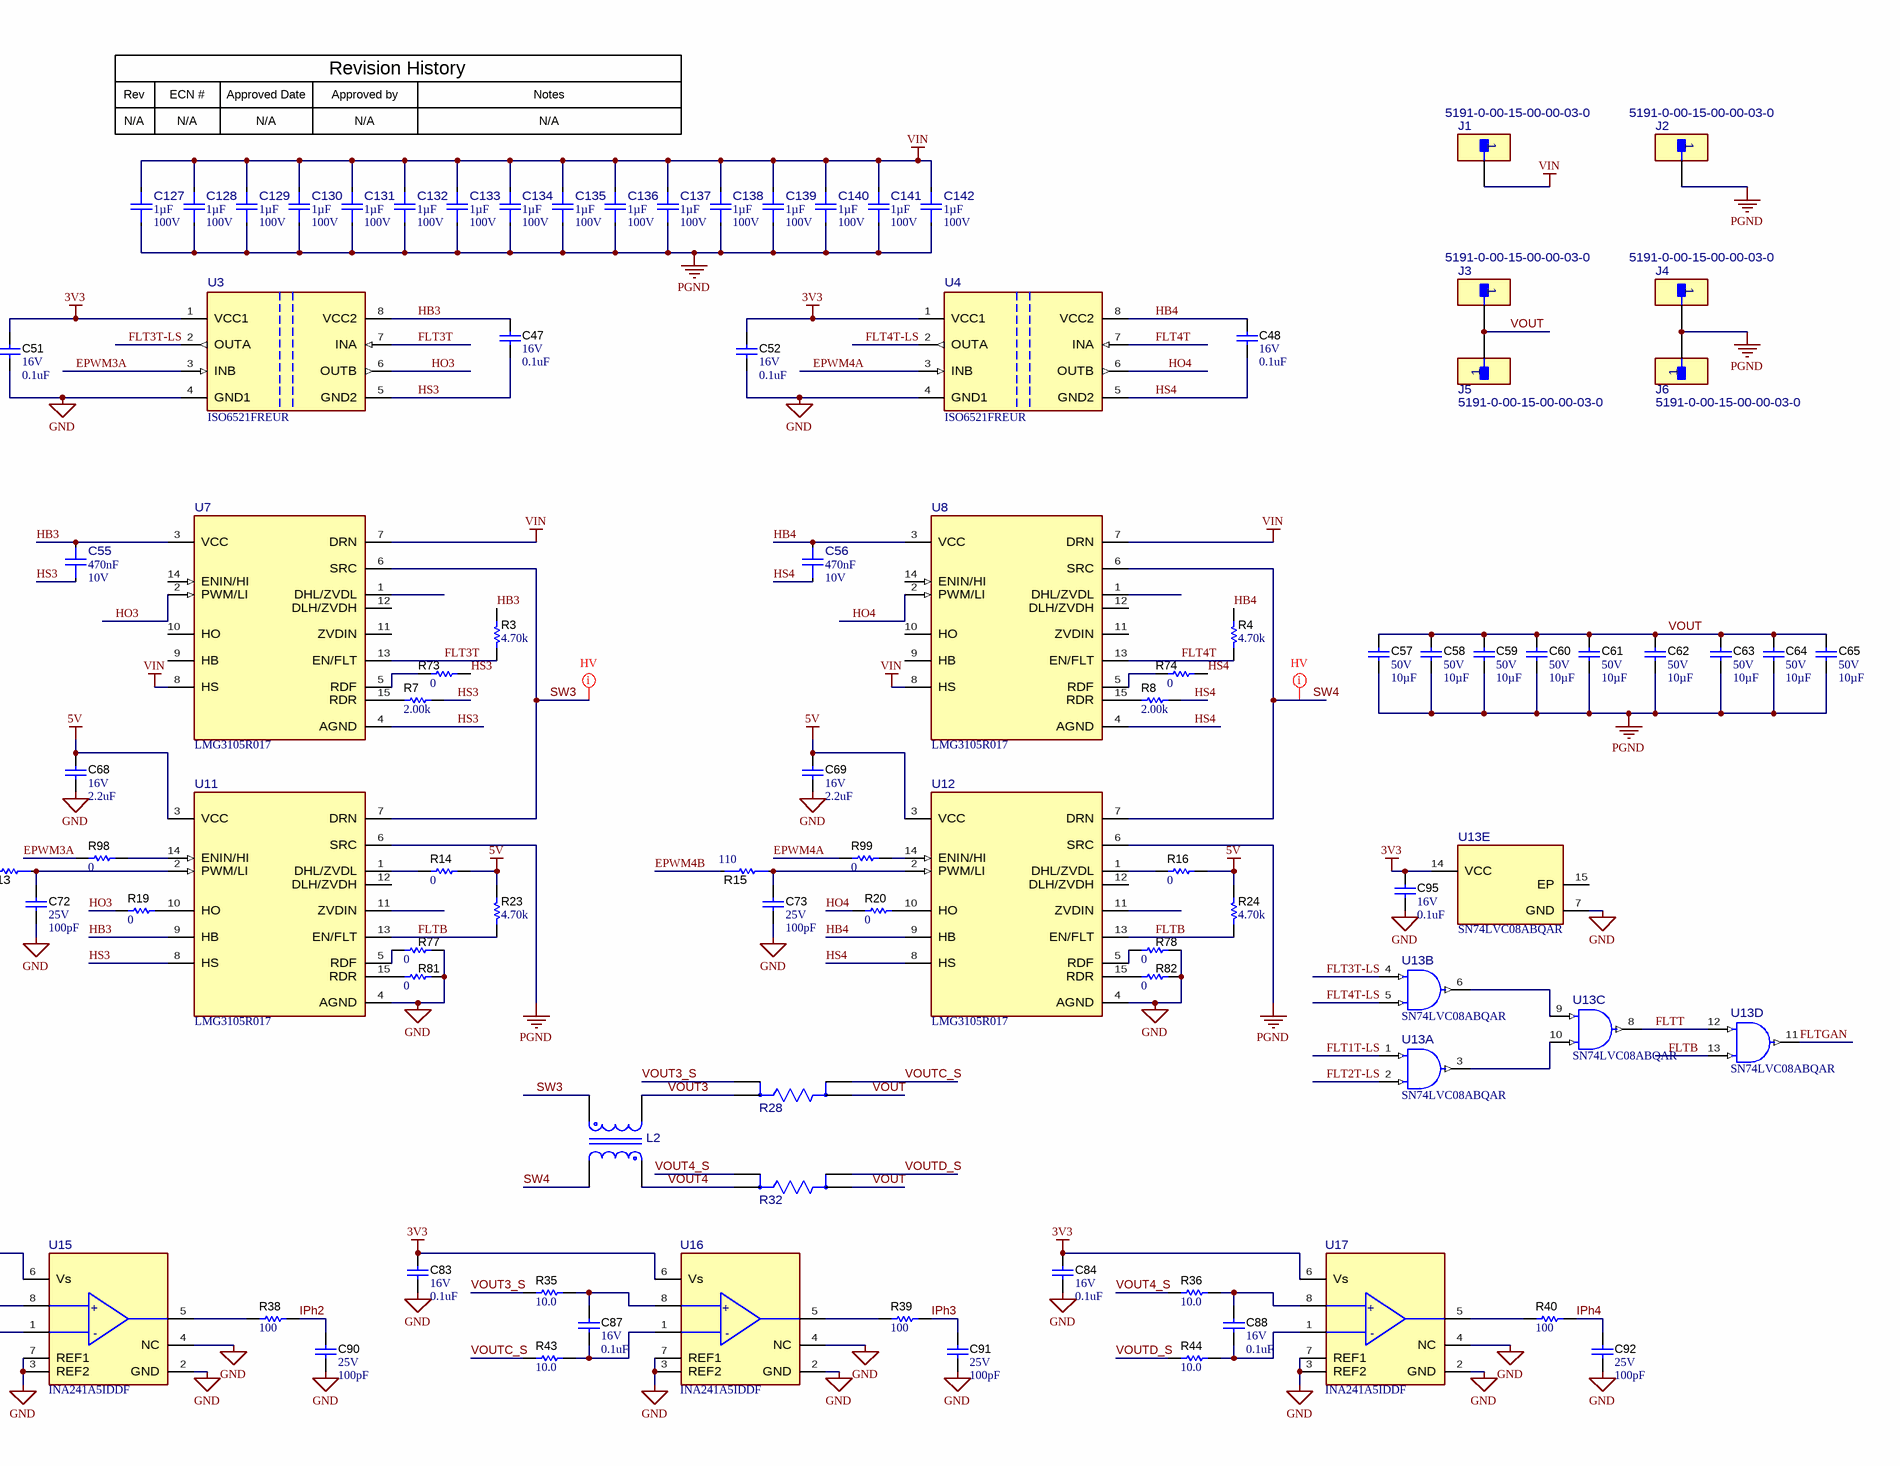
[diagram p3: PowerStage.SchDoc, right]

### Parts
C7  VDC_V: 100V  ValueDisplayed: 10uF  [FP-C3225X7R2A106K250AC_1210-MFG]  (hidden comment: C3225X7R2A106K250AC)
C9  VDC_V: 100V  ValueDisplayed: 10uF  [FP-C3225X7R2A106K250AC_1210-MFG]  (hidden comment: C3225X7R2A106K250AC)
C10  VDC_V: 100V  ValueDisplayed: 10uF  [FP-C3225X7R2A106K250AC_1210-MFG]  (hidden comment: C3225X7R2A106K250AC)
C11  VDC_V: 100V  ValueDisplayed: 10uF  [FP-C3225X7R2A106K250AC_1210-MFG]  (hidden comment: C3225X7R2A106K250AC)
C12  VDC_V: 100V  ValueDisplayed: 10uF  [FP-C3225X7R2A106K250AC_1210-MFG]  (hidden comment: C3225X7R2A106K250AC)
C13  ValueDisplayed: 4.7uF  [FP-C2012X5R2A475K125AC_0805-MFG]  (hidden comment: C2012X5R2A475K125AC)
C14  ValueDisplayed: 4.7uF  [FP-C2012X5R2A475K125AC_0805-MFG]  (hidden comment: C2012X5R2A475K125AC)
C15  ValueDisplayed: 4.7uF  [FP-C2012X5R2A475K125AC_0805-MFG]  (hidden comment: C2012X5R2A475K125AC)
C16  ValueDisplayed: 4.7uF  [FP-C2012X5R2A475K125AC_0805-MFG]  (hidden comment: C2012X5R2A475K125AC)
C17  ValueDisplayed: 4.7uF  [FP-C2012X5R2A475K125AC_0805-MFG]  (hidden comment: C2012X5R2A475K125AC)
C18  ValueDisplayed: 4.7uF  [FP-C2012X5R2A475K125AC_0805-MFG]  (hidden comment: C2012X5R2A475K125AC)
C19  ValueDisplayed: 4.7uF  [FP-C2012X5R2A475K125AC_0805-MFG]  (hidden comment: C2012X5R2A475K125AC)
C20  ValueDisplayed: 4.7uF  [FP-C2012X5R2A475K125AC_0805-MFG]  (hidden comment: C2012X5R2A475K125AC)
C21  ValueDisplayed: 4.7uF  [FP-C2012X5R2A475K125AC_0805-MFG]  (hidden comment: C2012X5R2A475K125AC)
C22  ValueDisplayed: 4.7uF  [FP-C2012X5R2A475K125AC_0805-MFG]  (hidden comment: C2012X5R2A475K125AC)
C23  ValueDisplayed: 4.7uF  [FP-C2012X5R2A475K125AC_0805-MFG]  (hidden comment: C2012X5R2A475K125AC)
C24  ValueDisplayed: 4.7uF  [FP-C2012X5R2A475K125AC_0805-MFG]  (hidden comment: C2012X5R2A475K125AC)
C33  ValueDisplayed: 4.7uF  [FP-C2012X5R2A475K125AC_0805-MFG]  (hidden comment: C2012X5R2A475K125AC)
C34  ValueDisplayed: 4.7uF  [FP-C2012X5R2A475K125AC_0805-MFG]  (hidden comment: C2012X5R2A475K125AC)
C35  ValueDisplayed: 4.7uF  [FP-C2012X5R2A475K125AC_0805-MFG]  (hidden comment: C2012X5R2A475K125AC)
C36  ValueDisplayed: 4.7uF  [FP-C2012X5R2A475K125AC_0805-MFG]  (hidden comment: C2012X5R2A475K125AC)
C37  ValueDisplayed: 4.7uF  [FP-C2012X5R2A475K125AC_0805-MFG]  (hidden comment: C2012X5R2A475K125AC)
C38  ValueDisplayed: 4.7uF  [FP-C2012X5R2A475K125AC_0805-MFG]  (hidden comment: C2012X5R2A475K125AC)
C39  ValueDisplayed: 4.7uF  [FP-C2012X5R2A475K125AC_0805-MFG]  (hidden comment: C2012X5R2A475K125AC)
C40  ValueDisplayed: 4.7uF  [FP-C2012X5R2A475K125AC_0805-MFG]  (hidden comment: C2012X5R2A475K125AC)
C41  ValueDisplayed: 4.7uF  [FP-C2012X5R2A475K125AC_0805-MFG]  (hidden comment: C2012X5R2A475K125AC)
C42  ValueDisplayed: 4.7uF  [FP-C2012X5R2A475K125AC_0805-MFG]  (hidden comment: C2012X5R2A475K125AC)
C43  ValueDisplayed: 4.7uF  [FP-C2012X5R2A475K125AC_0805-MFG]  (hidden comment: C2012X5R2A475K125AC)
C44  ValueDisplayed: 4.7uF  [FP-C2012X5R2A475K125AC_0805-MFG]  (hidden comment: C2012X5R2A475K125AC)
C45  VDC_V: 16V  ValueDisplayed: 0.1uF  [0201]  (hidden comment: GRM033Z71C104KE14D)
C46  VDC_V: 16V  ValueDisplayed: 0.1uF  [0201]  (hidden comment: GRM033Z71C104KE14D)
C47  VDC_V: 16V  ValueDisplayed: 0.1uF  [0201]  (hidden comment: GRM033Z71C104KE14D)
C48  VDC_V: 16V  ValueDisplayed: 0.1uF  [0201]  (hidden comment: GRM033Z71C104KE14D)
C49  VDC_V: 16V  ValueDisplayed: 0.1uF  [0201]  (hidden comment: GRM033Z71C104KE14D)
C50  VDC_V: 16V  ValueDisplayed: 0.1uF  [0201]  (hidden comment: GRM033Z71C104KE14D)
C51  VDC_V: 16V  ValueDisplayed: 0.1uF  [0201]  (hidden comment: GRM033Z71C104KE14D)
C52  VDC_V: 16V  ValueDisplayed: 0.1uF  [0201]  (hidden comment: GRM033Z71C104KE14D)
C53  ValueDisplayed: 470nF  VDC_V: 10V  [FP-GRT155R71A474KE01D_0402-MFG]  (hidden comment: GRT155R71A474KE01D)
C54  ValueDisplayed: 470nF  VDC_V: 10V  [FP-GRT155R71A474KE01D_0402-MFG]  (hidden comment: GRT155R71A474KE01D)
C55  ValueDisplayed: 470nF  VDC_V: 10V  [FP-GRT155R71A474KE01D_0402-MFG]  (hidden comment: GRT155R71A474KE01D)
C56  ValueDisplayed: 470nF  VDC_V: 10V  [FP-GRT155R71A474KE01D_0402-MFG]  (hidden comment: GRT155R71A474KE01D)
C57  VDC_V: 50V  ValueDisplayed: 10µF  [1210_270]  (hidden comment: CL32B106KBJNNWE)
C58  VDC_V: 50V  ValueDisplayed: 10µF  [1210_270]  (hidden comment: CL32B106KBJNNWE)
C59  VDC_V: 50V  ValueDisplayed: 10µF  [1210_270]  (hidden comment: CL32B106KBJNNWE)
C60  VDC_V: 50V  ValueDisplayed: 10µF  [1210_270]  (hidden comment: CL32B106KBJNNWE)
C61  VDC_V: 50V  ValueDisplayed: 10µF  [1210_270]  (hidden comment: CL32B106KBJNNWE)
C62  VDC_V: 50V  ValueDisplayed: 10µF  [1210_270]  (hidden comment: CL32B106KBJNNWE)
C63  VDC_V: 50V  ValueDisplayed: 10µF  [1210_270]  (hidden comment: CL32B106KBJNNWE)
C64  VDC_V: 50V  ValueDisplayed: 10µF  [1210_270]  (hidden comment: CL32B106KBJNNWE)
C65  VDC_V: 50V  ValueDisplayed: 10µF  [1210_270]  (hidden comment: CL32B106KBJNNWE)
C66  VDC_V: 16V  ValueDisplayed: 2.2uF  [0402S]  (hidden comment: C1005X5R1C225K050BC)
C67  VDC_V: 16V  ValueDisplayed: 2.2uF  [0402S]  (hidden comment: C1005X5R1C225K050BC)
C68  VDC_V: 16V  ValueDisplayed: 2.2uF  [0402S]  (hidden comment: C1005X5R1C225K050BC)
C69  VDC_V: 16V  ValueDisplayed: 2.2uF  [0402S]  (hidden comment: C1005X5R1C225K050BC)
C70  VDC_V: 25V  ValueDisplayed: 100pF  [0201_033]  (hidden comment: GRM033R71E101JA01D)
C71  VDC_V: 25V  ValueDisplayed: 100pF  [0201_033]  (hidden comment: GRM033R71E101JA01D)
C72  VDC_V: 25V  ValueDisplayed: 100pF  [0201_033]  (hidden comment: GRM033R71E101JA01D)
C73  VDC_V: 25V  ValueDisplayed: 100pF  [0201_033]  (hidden comment: GRM033R71E101JA01D)
C81  VDC_V: 16V  ValueDisplayed: 0.1uF  [0201]  (hidden comment: GRM033Z71C104KE14D)
C82  VDC_V: 16V  ValueDisplayed: 0.1uF  [0201]  (hidden comment: GRM033Z71C104KE14D)
C83  VDC_V: 16V  ValueDisplayed: 0.1uF  [0201]  (hidden comment: GRM033Z71C104KE14D)
C84  VDC_V: 16V  ValueDisplayed: 0.1uF  [0201]  (hidden comment: GRM033Z71C104KE14D)
C85  VDC_V: 16V  ValueDisplayed: 0.1uF  [0402S]  (hidden comment: GRM155R71C104KA88D)
C86  VDC_V: 16V  ValueDisplayed: 0.1uF  [0402S]  (hidden comment: GRM155R71C104KA88D)
C87  VDC_V: 16V  ValueDisplayed: 0.1uF  [0402S]  (hidden comment: GRM155R71C104KA88D)
C88  VDC_V: 16V  ValueDisplayed: 0.1uF  [0402S]  (hidden comment: GRM155R71C104KA88D)
C89  VDC_V: 25V  ValueDisplayed: 100pF  [0201_033]  (hidden comment: GRM033R71E101JA01D)
C90  VDC_V: 25V  ValueDisplayed: 100pF  [0201_033]  (hidden comment: GRM033R71E101JA01D)
C91  VDC_V: 25V  ValueDisplayed: 100pF  [0201_033]  (hidden comment: GRM033R71E101JA01D)
C92  VDC_V: 25V  ValueDisplayed: 100pF  [0201_033]  (hidden comment: GRM033R71E101JA01D)
C95  VDC_V: 16V  ValueDisplayed: 0.1uF  [0201]  (hidden comment: GRM033Z71C104KE14D)
C127  Cap_F: 1µF  VDC_V: 100V  [FP-C1608X7R2A105K080AC_0603-MFG]  (hidden comment: C1608X7R2A105K080AC)
C128  Cap_F: 1µF  VDC_V: 100V  [FP-C1608X7R2A105K080AC_0603-MFG]  (hidden comment: C1608X7R2A105K080AC)
C129  Cap_F: 1µF  VDC_V: 100V  [FP-C1608X7R2A105K080AC_0603-MFG]  (hidden comment: C1608X7R2A105K080AC)
C130  Cap_F: 1µF  VDC_V: 100V  [FP-C1608X7R2A105K080AC_0603-MFG]  (hidden comment: C1608X7R2A105K080AC)
C131  Cap_F: 1µF  VDC_V: 100V  [FP-C1608X7R2A105K080AC_0603-MFG]  (hidden comment: C1608X7R2A105K080AC)
C132  Cap_F: 1µF  VDC_V: 100V  [FP-C1608X7R2A105K080AC_0603-MFG]  (hidden comment: C1608X7R2A105K080AC)
C133  Cap_F: 1µF  VDC_V: 100V  [FP-C1608X7R2A105K080AC_0603-MFG]  (hidden comment: C1608X7R2A105K080AC)
C134  Cap_F: 1µF  VDC_V: 100V  [FP-C1608X7R2A105K080AC_0603-MFG]  (hidden comment: C1608X7R2A105K080AC)
C135  Cap_F: 1µF  VDC_V: 100V  [FP-C1608X7R2A105K080AC_0603-MFG]  (hidden comment: C1608X7R2A105K080AC)
C136  Cap_F: 1µF  VDC_V: 100V  [FP-C1608X7R2A105K080AC_0603-MFG]  (hidden comment: C1608X7R2A105K080AC)
C137  Cap_F: 1µF  VDC_V: 100V  [FP-C1608X7R2A105K080AC_0603-MFG]  (hidden comment: C1608X7R2A105K080AC)
C138  Cap_F: 1µF  VDC_V: 100V  [FP-C1608X7R2A105K080AC_0603-MFG]  (hidden comment: C1608X7R2A105K080AC)
C139  Cap_F: 1µF  VDC_V: 100V  [FP-C1608X7R2A105K080AC_0603-MFG]  (hidden comment: C1608X7R2A105K080AC)
C140  Cap_F: 1µF  VDC_V: 100V  [FP-C1608X7R2A105K080AC_0603-MFG]  (hidden comment: C1608X7R2A105K080AC)
C141  Cap_F: 1µF  VDC_V: 100V  [FP-C1608X7R2A105K080AC_0603-MFG]  (hidden comment: C1608X7R2A105K080AC)
C142  Cap_F: 1µF  VDC_V: 100V  [FP-C1608X7R2A105K080AC_0603-MFG]  (hidden comment: C1608X7R2A105K080AC)
J1  5191-0-00-15-00-00-03-0  [FP-5191-0-00-15-00-00-03-0_CONN_PIN-MFG]
J2  5191-0-00-15-00-00-03-0  [FP-5191-0-00-15-00-00-03-0_CONN_PIN-MFG]
J3  5191-0-00-15-00-00-03-0  [FP-5191-0-00-15-00-00-03-0_CONN_PIN-MFG]
J4  5191-0-00-15-00-00-03-0  [FP-5191-0-00-15-00-00-03-0_CONN_PIN-MFG]
J5  5191-0-00-15-00-00-03-0  [FP-5191-0-00-15-00-00-03-0_CONN_PIN-MFG]
J6  5191-0-00-15-00-00-03-0  [FP-5191-0-00-15-00-00-03-0_CONN_PIN-MFG]
L1  ERUC23-2R8K  [FP-ERUC23-2R8K_SMT_IND_26MM8_13MM8-MFG]  (value not drawn)
L2  ERUC23-2R8K  [FP-ERUC23-2R8K_SMT_IND_26MM8_13MM8-MFG]  (value not drawn)
NT1  Net-Tie  [Net-Tie_10mil]  (net tie, no BOM)
R1  ValueDisplayed: 4.70k  [0201_033]  (hidden comment: CRCW02014K70FKED)
R2  ValueDisplayed: 4.70k  [0201_033]  (hidden comment: CRCW02014K70FKED)
R3  ValueDisplayed: 4.70k  [0201_033]  (hidden comment: CRCW02014K70FKED)
R4  ValueDisplayed: 4.70k  [0201_033]  (hidden comment: CRCW02014K70FKED)
R5  ValueDisplayed: 2.00k  [0201]  (hidden comment: CRCW02012K00FKED)
R6  ValueDisplayed: 2.00k  [0201]  (hidden comment: CRCW02012K00FKED)
R7  ValueDisplayed: 2.00k  [0201]  (hidden comment: CRCW02012K00FKED)
R8  ValueDisplayed: 2.00k  [0201]  (hidden comment: CRCW02012K00FKED)
R9  value 110  [FP-ERJ-1GNF1100C_0201-MFG]  (hidden comment: ERJ-1GNF1100C)
R10  ValueDisplayed: 0  [0201_Silk]  (hidden comment: CRCW02010000Z0ED)
R11  value 110  [FP-ERJ-1GNF1100C_0201-MFG]  (hidden comment: ERJ-1GNF1100C)
R12  ValueDisplayed: 0  [0201_Silk]  (hidden comment: CRCW02010000Z0ED)
R13  value 110  [FP-ERJ-1GNF1100C_0201-MFG]  (hidden comment: ERJ-1GNF1100C)
R14  ValueDisplayed: 0  [0201_Silk]  (hidden comment: CRCW02010000Z0ED)
R15  value 110  [FP-ERJ-1GNF1100C_0201-MFG]  (hidden comment: ERJ-1GNF1100C)
R16  ValueDisplayed: 0  [0201_Silk]  (hidden comment: CRCW02010000Z0ED)
R17  ValueDisplayed: 0  [0201_Silk]  (hidden comment: CRCW02010000Z0ED)
R18  ValueDisplayed: 0  [0201_Silk]  (hidden comment: CRCW02010000Z0ED)
R19  ValueDisplayed: 0  [0201_Silk]  (hidden comment: CRCW02010000Z0ED)
R20  ValueDisplayed: 0  [0201_Silk]  (hidden comment: CRCW02010000Z0ED)
R21  ValueDisplayed: 4.70k  [0201_033]  (hidden comment: CRCW02014K70FKED)
R22  ValueDisplayed: 4.70k  [0201_033]  (hidden comment: CRCW02014K70FKED)
R23  ValueDisplayed: 4.70k  [0201_033]  (hidden comment: CRCW02014K70FKED)
R24  ValueDisplayed: 4.70k  [0201_033]  (hidden comment: CRCW02014K70FKED)
R27  WSK1216L2000FEA  [FP-WSK1216L2000FEA_1612-MFG]  (value not drawn)
R28  WSK1216L2000FEA  [FP-WSK1216L2000FEA_1612-MFG]  (value not drawn)
R31  WSK1216L2000FEA  [FP-WSK1216L2000FEA_1612-MFG]  (value not drawn)
R32  WSK1216L2000FEA  [FP-WSK1216L2000FEA_1612-MFG]  (value not drawn)
R33  ValueDisplayed: 10.0  [0402]  (hidden comment: CRCW040210R0FKED)
R34  ValueDisplayed: 10.0  [0402]  (hidden comment: CRCW040210R0FKED)
R35  ValueDisplayed: 10.0  [0402]  (hidden comment: CRCW040210R0FKED)
R36  ValueDisplayed: 10.0  [0402]  (hidden comment: CRCW040210R0FKED)
R37  ValueDisplayed: 100  [0201]  (hidden comment: CRCW0201100RFKED)
R38  ValueDisplayed: 100  [0201]  (hidden comment: CRCW0201100RFKED)
R39  ValueDisplayed: 100  [0201]  (hidden comment: CRCW0201100RFKED)
R40  ValueDisplayed: 100  [0201]  (hidden comment: CRCW0201100RFKED)
R41  ValueDisplayed: 10.0  [0402]  (hidden comment: CRCW040210R0FKED)
R42  ValueDisplayed: 10.0  [0402]  (hidden comment: CRCW040210R0FKED)
R43  ValueDisplayed: 10.0  [0402]  (hidden comment: CRCW040210R0FKED)
R44  ValueDisplayed: 10.0  [0402]  (hidden comment: CRCW040210R0FKED)
R71  ValueDisplayed: 0  [0201_Silk]  (hidden comment: CRCW02010000Z0ED)
R72  ValueDisplayed: 0  [0201_Silk]  (hidden comment: CRCW02010000Z0ED)
R73  ValueDisplayed: 0  [0201_Silk]  (hidden comment: CRCW02010000Z0ED)
R74  ValueDisplayed: 0  [0201_Silk]  (hidden comment: CRCW02010000Z0ED)
R75  ValueDisplayed: 0  [0201_Silk]  (hidden comment: CRCW02010000Z0ED)
R76  ValueDisplayed: 0  [0201_Silk]  (hidden comment: CRCW02010000Z0ED)
R77  ValueDisplayed: 0  [0201_Silk]  (hidden comment: CRCW02010000Z0ED)
R78  ValueDisplayed: 0  [0201_Silk]  (hidden comment: CRCW02010000Z0ED)
R79  ValueDisplayed: 0  [0201_Silk]  (hidden comment: CRCW02010000Z0ED)
R80  ValueDisplayed: 0  [0201_Silk]  (hidden comment: CRCW02010000Z0ED)
R81  ValueDisplayed: 0  [0201_Silk]  (hidden comment: CRCW02010000Z0ED)
R82  ValueDisplayed: 0  [0201_Silk]  (hidden comment: CRCW02010000Z0ED)
R96  ValueDisplayed: 0  [0201_Silk]  (hidden comment: CRCW02010000Z0ED)
R97  ValueDisplayed: 0  [0201_Silk]  (hidden comment: CRCW02010000Z0ED)
R98  ValueDisplayed: 0  [0201_Silk]  (hidden comment: CRCW02010000Z0ED)
R99  ValueDisplayed: 0  [0201_Silk]  (hidden comment: CRCW02010000Z0ED)
U1  ISO6521FREUR  [REU0008A-MFG]
U2  ISO6521FREUR  [REU0008A-MFG]
U3  ISO6521FREUR  [REU0008A-MFG]
U4  ISO6521FREUR  [REU0008A-MFG]
U5  LMG3105R017  [VBE0015A-MFG]
U6  LMG3105R017  [VBE0015A-MFG]
U7  LMG3105R017  [VBE0015A-MFG]
U8  LMG3105R017  [VBE0015A-MFG]
U9  LMG3105R017  [VBE0015A-MFG]
U10  LMG3105R017  [VBE0015A-MFG]
U11  LMG3105R017  [VBE0015A-MFG]
U12  LMG3105R017  [VBE0015A-MFG]
U13  SN74LVC08ABQAR  [BQA0014A-MFG]  (parts A,B,C,D,E of 5)
U14  INA241A5IDDF  [DDF0008A-MFG]
U15  INA241A5IDDF  [DDF0008A-MFG]
U16  INA241A5IDDF  [DDF0008A-MFG]
U17  INA241A5IDDF  [DDF0008A-MFG]

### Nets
3V3: C49.1 C50.1 C51.1 C52.1 C81.1 C82.1 C83.1 C84.1 C95.1 U1.1(VCC1) U2.1(VCC1) U3.1(VCC1) U4.1(VCC1) U13.14(VCC) U14.6(Vs) U15.6(Vs) U16.6(Vs) U17.6(Vs)
5V: C66.1 C67.1 C68.1 C69.1 R10.1 R12.1 R14.1 R16.1 R21.2 R22.2 R23.2 R24.2 U9.3(VCC) U10.3(VCC) U11.3(VCC) U12.3(VCC)
GND: C49.2 C50.2 C51.2 C52.2 C66.2 C67.2 C68.2 C69.2 C70.2 C71.2 C72.2 C73.2 C81.2 C82.2 C83.2 C84.2 C89.2 C90.2 C91.2 C92.2 C95.2 NT1.1 R75.1 R76.1 R77.1 R78.1 R79.1 R80.1 R81.1 R82.1 U1.4(GND1) U2.4(GND1) U3.4(GND1) U4.4(GND1) U9.4(AGND) U10.4(AGND) U11.4(AGND) U12.4(AGND) U13.7(GND) U14.2(GND) U14.3(REF2) U14.4(NC) U14.7(REF1) U15.2(GND) U15.3(REF2) U15.4(NC) U15.7(REF1) U16.2(GND) U16.3(REF2) U16.4(NC) U16.7(REF1) U17.2(GND) U17.3(REF2) U17.4(NC) U17.7(REF1)
PGND: C7.1 C9.1 C10.1 C11.1 C12.1 C13.1 C14.1 C15.1 C16.1 C17.1 C18.1 C19.1 C20.1 C21.1 C22.1 C23.1 C24.1 C33.1 C34.1 C35.1 C36.1 C37.1 C38.1 C39.1 C40.1 C41.1 C42.1 C43.1 C44.1 C57.2 C58.2 C59.2 C60.2 C61.2 C62.2 C63.2 C64.2 C65.2 C127.1 C128.1 C129.1 C130.1 C131.1 C132.1 C133.1 C134.1 C135.1 C136.1 C137.1 C138.1 C139.1 C140.1 C141.1 C142.1 J2.1 J4.1 J6.1 NT1.2 U9.6(SRC) U10.6(SRC) U11.6(SRC) U12.6(SRC)
VIN: C7.2 C9.2 C10.2 C11.2 C12.2 C13.2 C14.2 C15.2 C16.2 C17.2 C18.2 C19.2 C20.2 C21.2 C22.2 C23.2 C24.2 C33.2 C34.2 C35.2 C36.2 C37.2 C38.2 C39.2 C40.2 C41.2 C42.2 C43.2 C44.2 C127.2 C128.2 C129.2 C130.2 C131.2 C132.2 C133.2 C134.2 C135.2 C136.2 C137.2 C138.2 C139.2 C140.2 C141.2 C142.2 J1.1 U5.7(DRN) U5.8(HS) U6.7(DRN) U6.8(HS) U7.7(DRN) U7.8(HS) U8.7(DRN) U8.8(HS)
EPWM1A: R96.2 U1.3(INB)
EPWM1B: R9.1
EPWM2A: R97.2 U2.3(INB)
EPWM2B: R11.1
EPWM3A: R98.2 U3.3(INB)
EPWM3B: R13.1
EPWM4A: R99.2 U4.3(INB)
EPWM4B: R15.1
FLT1T: R1.2 U1.7(INA) U5.13(EN/FLT)
FLT1T-LS: U1.2(OUTA) U13.1(1A)
FLT2T: R2.2 U2.7(INA) U6.13(EN/FLT)
FLT2T-LS: U2.2(OUTA) U13.2(1B)
FLT3T: R3.2 U3.7(INA) U7.13(EN/FLT)
FLT3T-LS: U3.2(OUTA) U13.4(2A)
FLT4T: R4.2 U4.7(INA) U8.13(EN/FLT)
FLT4T-LS: U4.2(OUTA) U13.5(2B)
FLTB: R21.1 R22.1 R23.1 R24.1 U9.13(EN/FLT) U10.13(EN/FLT) U11.13(EN/FLT) U12.13(EN/FLT) U13.13(4B)
FLTGAN: U13.11(4Y)
FLTT: U13.8(3Y) U13.12(4A)
HB1: C45.1 C53.2 R1.1 U1.8(VCC2) U5.3(VCC) U9.9(HB)
HB2: C46.1 C54.2 R2.1 U2.8(VCC2) U6.3(VCC) U10.9(HB)
HB3: C47.1 C55.2 R3.1 U3.8(VCC2) U7.3(VCC) U11.9(HB)
HB4: C48.1 C56.2 R4.1 U4.8(VCC2) U8.3(VCC) U12.9(HB)
HO1: R17.2 U1.6(OUTB) U5.2(PWM/LI)
HO2: R18.2 U2.6(OUTB) U6.2(PWM/LI)
HO3: R19.2 U3.6(OUTB) U7.2(PWM/LI)
HO4: R20.2 U4.6(OUTB) U8.2(PWM/LI)
HS1: C45.2 C53.1 R5.1 R71.1 U1.5(GND2) U5.4(AGND) U9.8(HS)
HS2: C46.2 C54.1 R6.1 R72.1 U2.5(GND2) U6.4(AGND) U10.8(HS)
HS3: C47.2 C55.1 R7.1 R73.1 U3.5(GND2) U7.4(AGND) U11.8(HS)
HS4: C48.2 C56.1 R8.1 R74.1 U4.5(GND2) U8.4(AGND) U12.8(HS)
IPh1: C89.1 R37.2
IPh2: C90.1 R38.2
IPh3: C91.1 R39.2
IPh4: C92.1 R40.2
SW1: L1.2 U5.6(SRC) U9.7(DRN)
SW2: L1.1 U6.6(SRC) U10.7(DRN)
SW3: L2.2 U7.6(SRC) U11.7(DRN)
SW4: L2.1 U8.6(SRC) U12.7(DRN)
VOUT: C57.1 C58.1 C59.1 C60.1 C61.1 C62.1 C63.1 C64.1 C65.1 J3.1 J5.1 R27.4 R28.4 R31.4 R32.4
VOUT1: L1.3 R27.3
VOUT1_S: R27.1 R33.1
VOUT2: L1.4 R31.3
VOUT2_S: R31.1 R34.1
VOUT3: L2.3 R28.3
VOUT3_S: R28.1 R35.1
VOUT4: L2.4 R32.3
VOUT4_S: R32.1 R36.1
VOUTA_S: R27.2 R41.1
VOUTB_S: R31.2 R42.1
VOUTC_S: R28.2 R43.1
VOUTD_S: R32.2 R44.1
NetC70_1: C70.1 R9.2 U9.2(PWM/LI)
NetC71_1: C71.1 R11.2 U10.2(PWM/LI)
NetC72_1: C72.1 R13.2 U11.2(PWM/LI)
NetC73_1: C73.1 R15.2 U12.2(PWM/LI)
NetC85_1: C85.1 R33.2 U14.8(IN+)
NetC85_2: C85.2 R41.2 U14.1(IN-)
NetC86_1: C86.1 R34.2 U15.8(IN+)
NetC86_2: C86.2 R42.2 U15.1(IN-)
NetC87_1: C87.1 R35.2 U16.8(IN+)
NetC87_2: C87.2 R43.2 U16.1(IN-)
NetC88_1: C88.1 R36.2 U17.8(IN+)
NetC88_2: C88.2 R44.2 U17.1(IN-)
NetR5_2: R5.2 U5.15(RDR)
NetR6_2: R6.2 U6.15(RDR)
NetR7_2: R7.2 U7.15(RDR)
NetR8_2: R8.2 U8.15(RDR)
NetR10_2: R10.2 U9.1(DHL/ZVDL)
NetR12_2: R12.2 U10.1(DHL/ZVDL)
NetR14_2: R14.2 U11.1(DHL/ZVDL)
NetR16_2: R16.2 U12.1(DHL/ZVDL)
NetR17_1: R17.1 U9.10(HO)
NetR18_1: R18.1 U10.10(HO)
NetR19_1: R19.1 U11.10(HO)
NetR20_1: R20.1 U12.10(HO)
NetR37_1: R37.1 U14.5(OUT)
NetR38_1: R38.1 U15.5(OUT)
NetR39_1: R39.1 U16.5(OUT)
NetR40_1: R40.1 U17.5(OUT)
NetR71_2: R71.2 U5.5(RDF)
NetR72_2: R72.2 U6.5(RDF)
NetR73_2: R73.2 U7.5(RDF)
NetR74_2: R74.2 U8.5(RDF)
NetR75_2: R75.2 U9.5(RDF)
NetR76_2: R76.2 U10.5(RDF)
NetR77_2: R77.2 U11.5(RDF)
NetR78_2: R78.2 U12.5(RDF)
NetR79_2: R79.2 U9.15(RDR)
NetR80_2: R80.2 U10.15(RDR)
NetR81_2: R81.2 U11.15(RDR)
NetR82_2: R82.2 U12.15(RDR)
NetR96_1: R96.1 U9.14(ENIN/HI)
NetR97_1: R97.1 U10.14(ENIN/HI)
NetR98_1: R98.1 U11.14(ENIN/HI)
NetR99_1: R99.1 U12.14(ENIN/HI)
NetU13_3: U13.3(1Y) U13.10(3B)
NetU13_6: U13.6(2Y) U13.9(3A)

Not connected (* = marked no-connect by the designer): U5 1(DHL/ZVDL) 9(HB) 10(HO) 11(ZVDIN) 12(DLH/ZVDH) 14(ENIN/HI); U6 1(DHL/ZVDL) 9(HB) 10(HO) 11(ZVDIN) 12(DLH/ZVDH) 14(ENIN/HI); U7 1(DHL/ZVDL) 9(HB) 10(HO) 11(ZVDIN) 12(DLH/ZVDH) 14(ENIN/HI); U8 1(DHL/ZVDL) 9(HB) 10(HO) 11(ZVDIN) 12(DLH/ZVDH) 14(ENIN/HI); U9 11(ZVDIN) 12(DLH/ZVDH); U10 11(ZVDIN) 12(DLH/ZVDH); U11 11(ZVDIN) 12(DLH/ZVDH); U12 11(ZVDIN) 12(DLH/ZVDH); U13 15(EP)

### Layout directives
net class HV: SW1, SW2, SW3, SW4, VIN

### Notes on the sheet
- Rev
- N/A
- ECN #
- Approved Date
- Approved by
- Revision History
- Notes

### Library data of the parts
C7 C9-C12 = CMP-0096021-1: 10 µF ±10% 100V Ceramic Capacitor X7R 1210 (3225 Metric); Manufacturer: TDK; Cap_F: 10µF; AEC Qualified: No; Value: 10µF; SizeZ_mm: 2.85mm; TempCo: 15%
C13-C24 C33-C44 = CMP-0098058-1: 4.7 µF ±10% 100V Ceramic Capacitor X5R 0805 (2012 Metric); Manufacturer: TDK; AEC Qualified: No; SizeZ_mm: 1.5mm; Value: 4.7µF; TempCo: 15%
C45-C52 C81-C84 C95 = CMP-0064970-1: as C94 on sheet Control
C53-C56 = CMP-0124903-1: Multi-Layer Ceramic Capacitor 470nF 10V X7R ±10% 0402 Paper T/R; Manufacturer: Murata; AEC Grade: Grade 1; AEC Qualified: Yes; SizeZ_mm: 0.55mm; TempCo: 0.15
C57-C65 = CMP-0079201-1: CAP, CERM, 10 µF, 50 V,+/- 10%, X7R, 1210; Manufacturer: Samsung Electro-Mechanics; TaMin_C: -55°C; ESR_ohm: 5m; Polarized: N; SizeAreaWB_mm2: 14.7; Value1: 0.005 ohm; U/M: EA; Value: 10uF; TaMax_C: 125°C; SizeZ_mm: 2.7; SizeX_mm: 3.2; SizeY_mm: 2.5; Cap_Case: 1210; SizeArea_mm2: 8; AEC Category: Q200
C66-C69 = CMP-0006275-2: as C120 on sheet Control
C70-C73 C89-C92 = CMP-0009762-1: CAP, CERM, 100 pF, 25 V, +/- 5%, C0G/NP0, 0201; Manufacturer: MuRata; TaMin_C: -55°C; Polarized: N; SizeAreaWB_mm2: 2.08; Value1: Unknown; U/M: EA; Value: 100pF; TaMax_C: 125°C; SizeZ_mm: 0.33; SizeX_mm: 0.6; SizeY_mm: 0.3; Cap_Case: 0201; SizeArea_mm2: 0.18; AEC Category: Q200
C85-C88 = CMP-0006641-2: CAP, CERM, 0.1 uF, 16 V, +/- 10%, X7R, 0402; Manufacturer: MuRata; TaMin_C: -55°C; Polarized: N; SizeAreaWB_mm2: 3; Value1: Unknown; U/M: EA; Value: 0.1uF; TaMax_C: 125°C; SizeZ_mm: 0.6; SizeX_mm: 1; SizeY_mm: 0.5; Cap_Case: 0402; Cap_F: 100nF; AEC Category: Q200
C127-C142 = CMP-0125726-1: 1 µF ±10% 100V Ceramic Capacitor X7R 0603 (1608 Metric); Manufacturer: TDK; AEC Qualified: No; SizeZ_mm: 1mm; TempCo: 15%; ValueDisplayed: 1uF; Value: 1µF
J1-J6 = CMP-0125276-1: as J7 on sheet Control
L1 L2 = CMP-0123560-1: Unshielded 2 Coil Inductor Array Inductance - Connected in Series 5.4 µH Inductance - Connected in Parallel 1.25mOhm DC Resistance (DCR) - Parallel Nonstandard, 4 Lead; Manufacturer: TDK; DCR_ohm: 1.25m; Ind_H: 5.4µH; SizeZ_mm: 14.1mm; Value: 5.4uH; AEC Qualified: Yes; AEC Grade: Grade 0; Irms: 27A; Isat: 55A; Material: Ferrite; Test Frequency: 100kHz; Tolerance_%: 10%
NT1 = CMP-0078142-6: Single point connection between nets.
R1-R4 R21-R24 = CMP-0027280-3: RES, 4.70 k, 1%, 0.05 W, 0201; Manufacturer: Vishay-Dale; Power_W: 50mW; TempCo: 100 ppm/C; Value_Code: 4k70; Value: 4.70k; Res_ohm: 4.7k; SizeX_mm: 0.6; SizeY_mm: 0.3; SizeZ_mm: 0.33; Value2: 0.05W; SizeArea_mm2: 0.18; AEC Qualified: N; VDC_V: 30V; AEC Category: Q200
R5-R8 = CMP-0027271-3: RES, 2.00 k, 1%, 0.05 W, 0201; Manufacturer: Vishay-Dale; Power_W: 50mW; TempCo: 100 ppm/C; Value_Code: 2k00; Value: 2.00k; EIA_Code: E96; Res_ohm: 2k; SizeX_mm: 0.6; SizeY_mm: 0.3; SizeZ_mm: 0.26; Value2: 0.05W; SizeArea_mm2: 0.18; AEC Qualified: N; VDC_V: 30V; AEC Category: Q200
R9 R11 R13 R15 = CMP-0126316-1: Res Thick Film 0201 110 Ohm 1% 0.05W(1/20W) ±200ppm/C Pad SMD Automotive T/R; Manufacturer: Panasonic Electronic Components; AEC Qualified: No; Power_W: 50mW; SizeZ_mm: 0.26mm; TempCo: 200ppm/°C; VDC_V: 25V
R10 R12 R14 R16-R20 R71-R82 R96-R99 = CMP-0027008-4: as R45 on sheet Control
R27 R28 R31 R32 = CMP-0037612-1: 0.2 mOhms ±1% 3W Chip Resistor Wide 1612 (3831 Metric), 1216 Anti-Sulfur, Automotive AEC-Q200, Current Sense, Pulse Withstanding Metal Element; Manufacturer: Vishay Dale; AEC Grade: Grade 0; AEC Qualified: Yes; Power_W: 8W; Res_ohm: 200µ; SizeZ_mm: 1.9mm; TempCo: 35ppm/°C; Value: 200µ
R33-R36 R41-R44 = CMP-0025963-3: RES, 10.0, 1%, 0.063 W, AEC-Q200 Grade 0, 0402; Manufacturer: Vishay-Dale; Power_W: 63mW; TempCo: 100 ppm/C; Value_Code: 10R0; Value: 10.0; EIA_Code: E96; Res_ohm: 10; SizeX_mm: 1; SizeY_mm: 0.5; SizeZ_mm: 0.6; Value2: 0.063W; AEC Qualified: Y; VDC_V: 50V; AEC Category: Q200; AEC Grade: 0
R37-R40 = CMP-0083836-1: RES, 100, 1%, 0.05 W, 0201; Manufacturer: Vishay-Semiconductor; Value_Code: 100R; SizeAreaWB_mm2: 2.08; SizeArea_mm2: 0.18; AEC Qualified: N; AEC Category: Q200; Value: 100; SizeZ_mm: 0.26; EIA_Code: E96; TempCo: 100 ppm/C; Power_W: 50mW; SizeY_mm: 0.3; Value2: 0.05W; SizeX_mm: 0.6
U1-U4 = CMP-0123447-1: General Purpose Dual-Channel Functional Isolators; Manufacturer: Texas Instruments; SizeZ_mm: 1.05mm; AEC Qualified: No; Max Supply Voltage: 5.5V; Min Supply Voltage: 1.71V; Standoff Height: 0mm; TaMax_C: +125°C; TaMin_C: -40°C; TJmax_C: +150°C
U5-U12 = CMP-0124166-1: Manufacturer: Texas Instruments; SizeZ_mm: 0.85mm; Standoff Height: 0mm
U13 = CMP-0125756-1: Four-channel two-input 1.65V to 3.6V AND gate 14-WQFN; Manufacturer: Texas Instruments; SizeZ_mm: 0.8mm; AEC Qualified: No; Nominal Supply Current: 1uA; Number Of Inputs: 2; Number Of Outputs: 1; PositionCount: 4; Propagation Delay: 2.6ns; Standoff Height: 0mm; TJmax_C: +150°C
U14-U17 = CMP-0093651-2: -4-V to 110-V, Bidirectional, Ultra-Precise Current Sense Amplifier With Enhanced PWM Rejection; Manufacturer: Texas Instruments; Bandwidth: 1MHz; TaMax_C: +125°C; Max Supply Voltage: 20V; Nominal Supply Current: 2.5mA; Number Of Channels: 1; Min Supply Voltage: 2.7V; Input Bias Current: 40uA; Response Time: 1.5us; AEC Category: Q200; TaMin_C: -40°C; Input Offset Voltage: 0.002mV; CompType: IC; AEC Qualified: No; TJmax_C: +150°C; SizeZ_mm: 1.1mm; Standoff Height: 0mm; Voltage Gain: 0.2V/mV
